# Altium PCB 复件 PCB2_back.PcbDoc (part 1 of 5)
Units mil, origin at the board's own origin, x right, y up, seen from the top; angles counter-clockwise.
Board outline 6299 x 3937 mil, 4 copper layers (TopLayer, GROUND, VCC, BottomLayer); 290 components, 470 nets, 2252 pads, 827 vias.
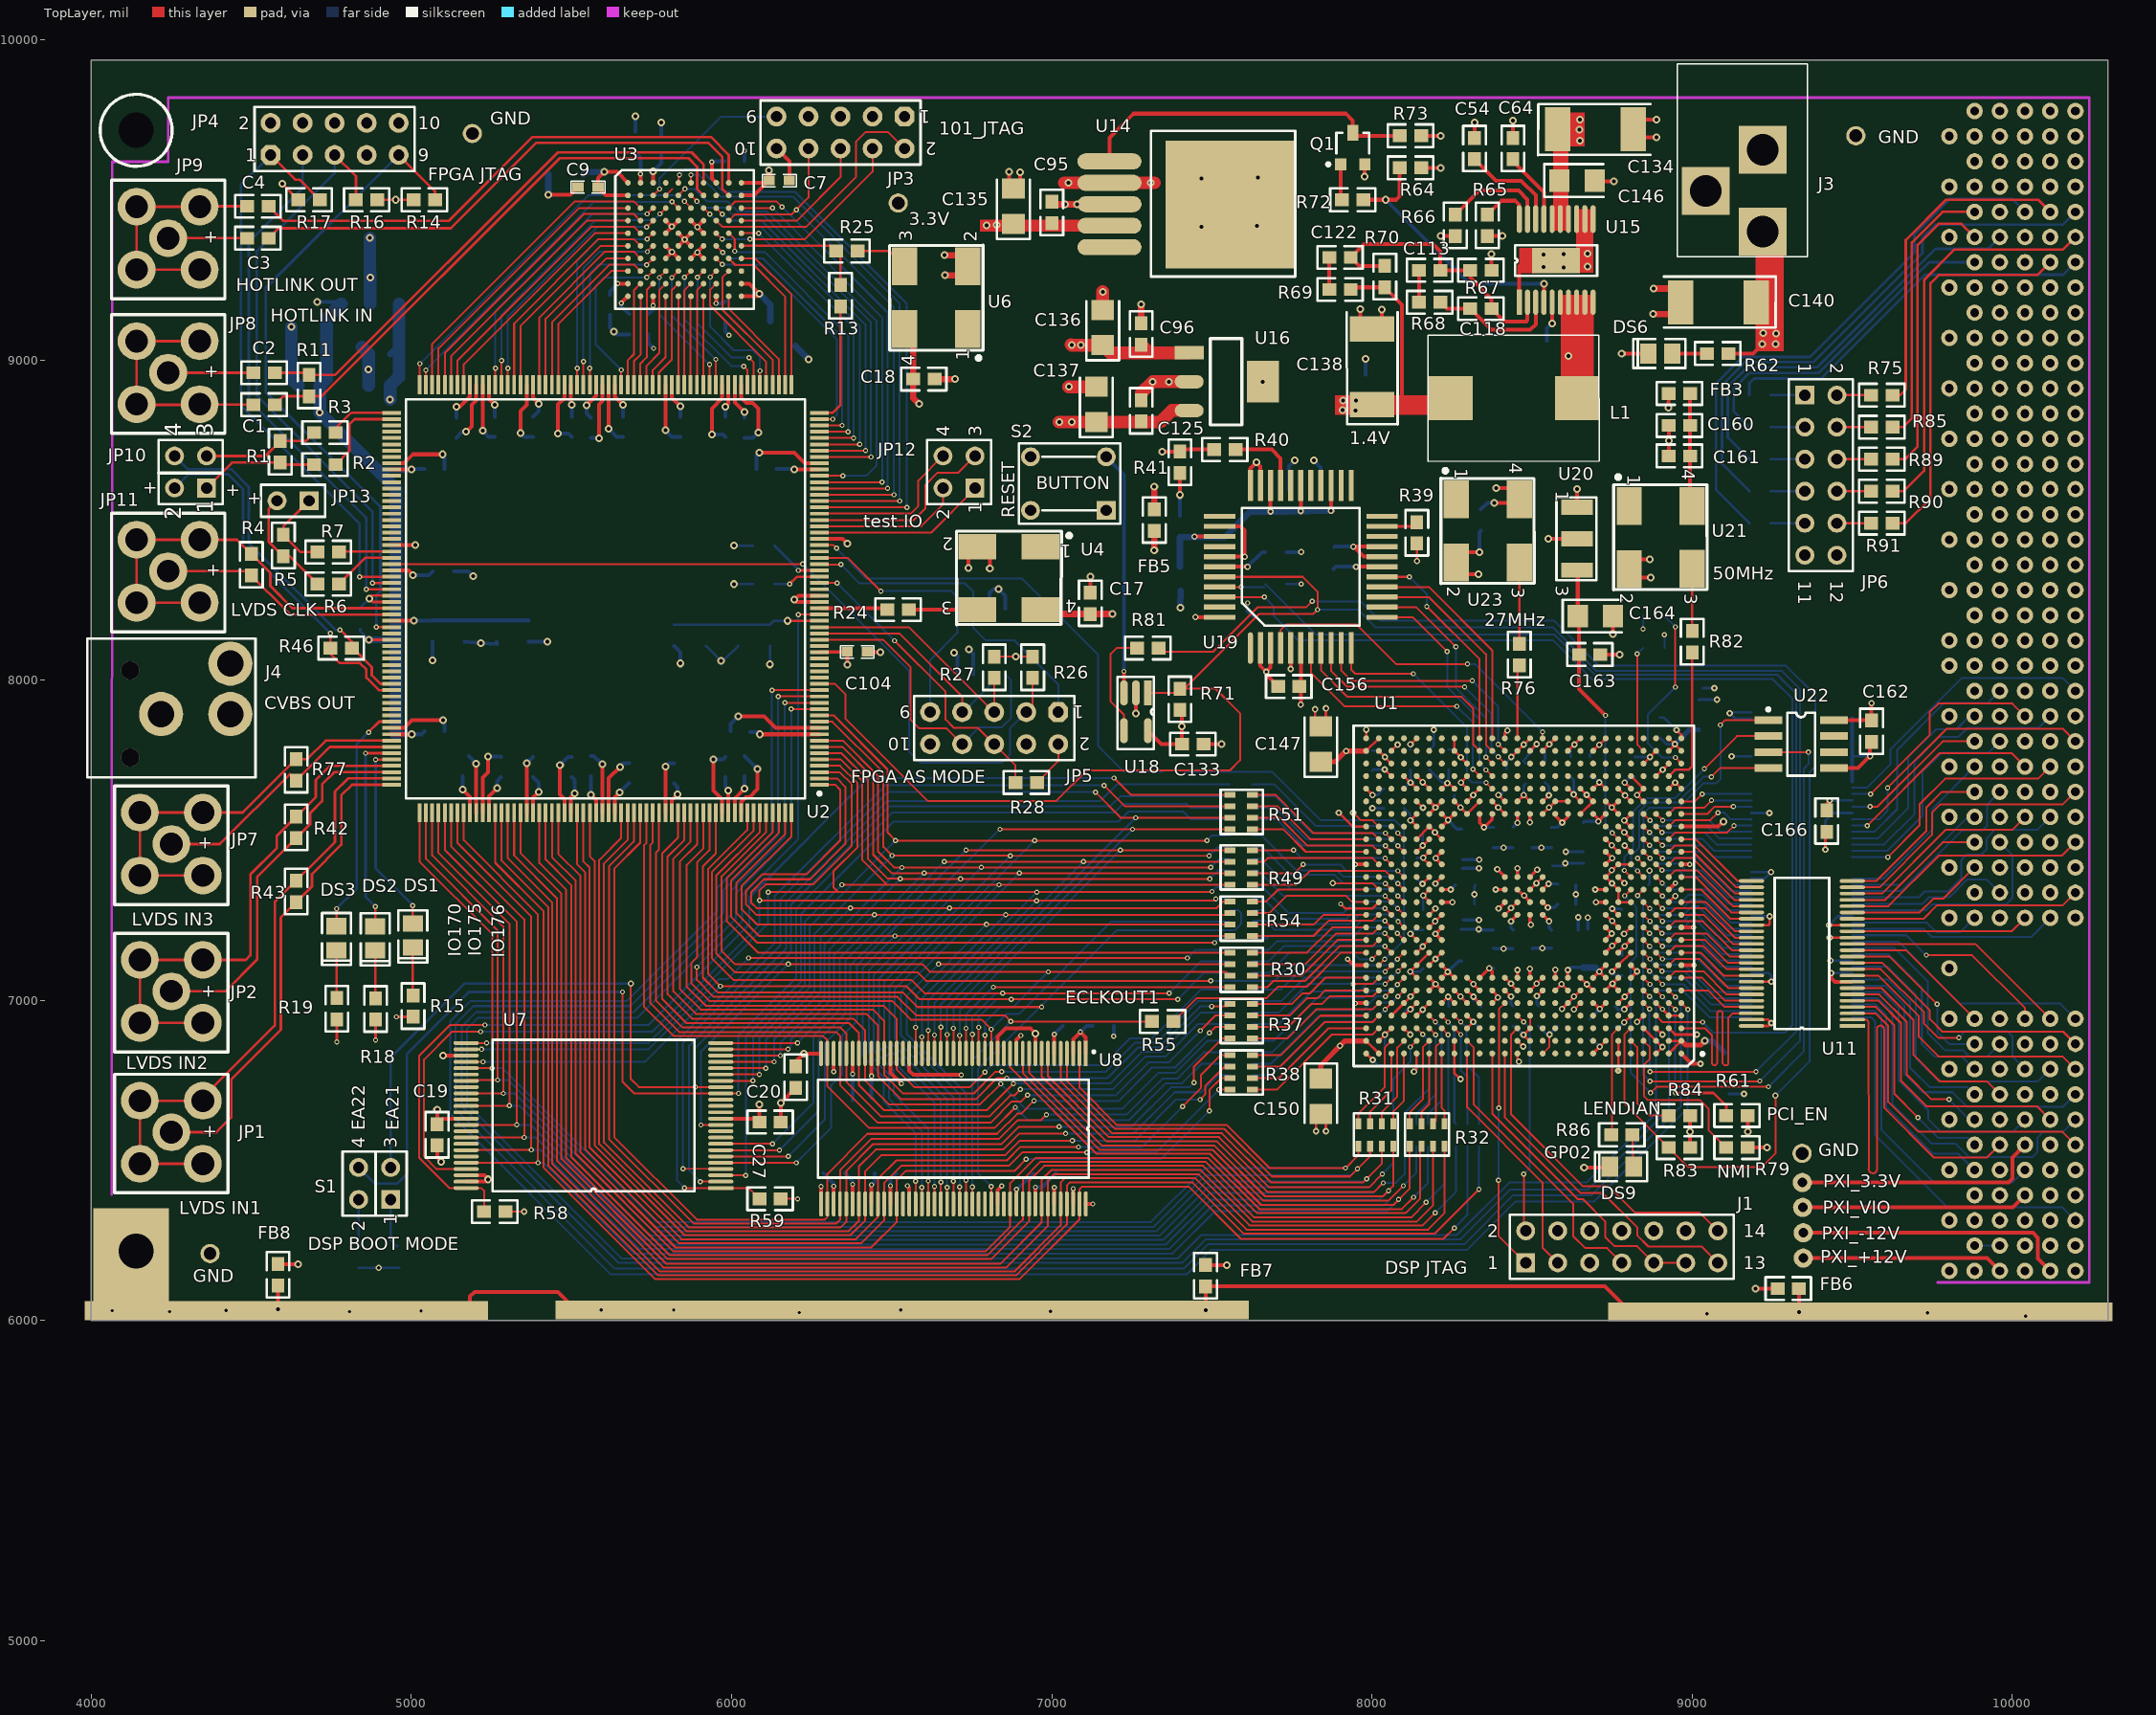
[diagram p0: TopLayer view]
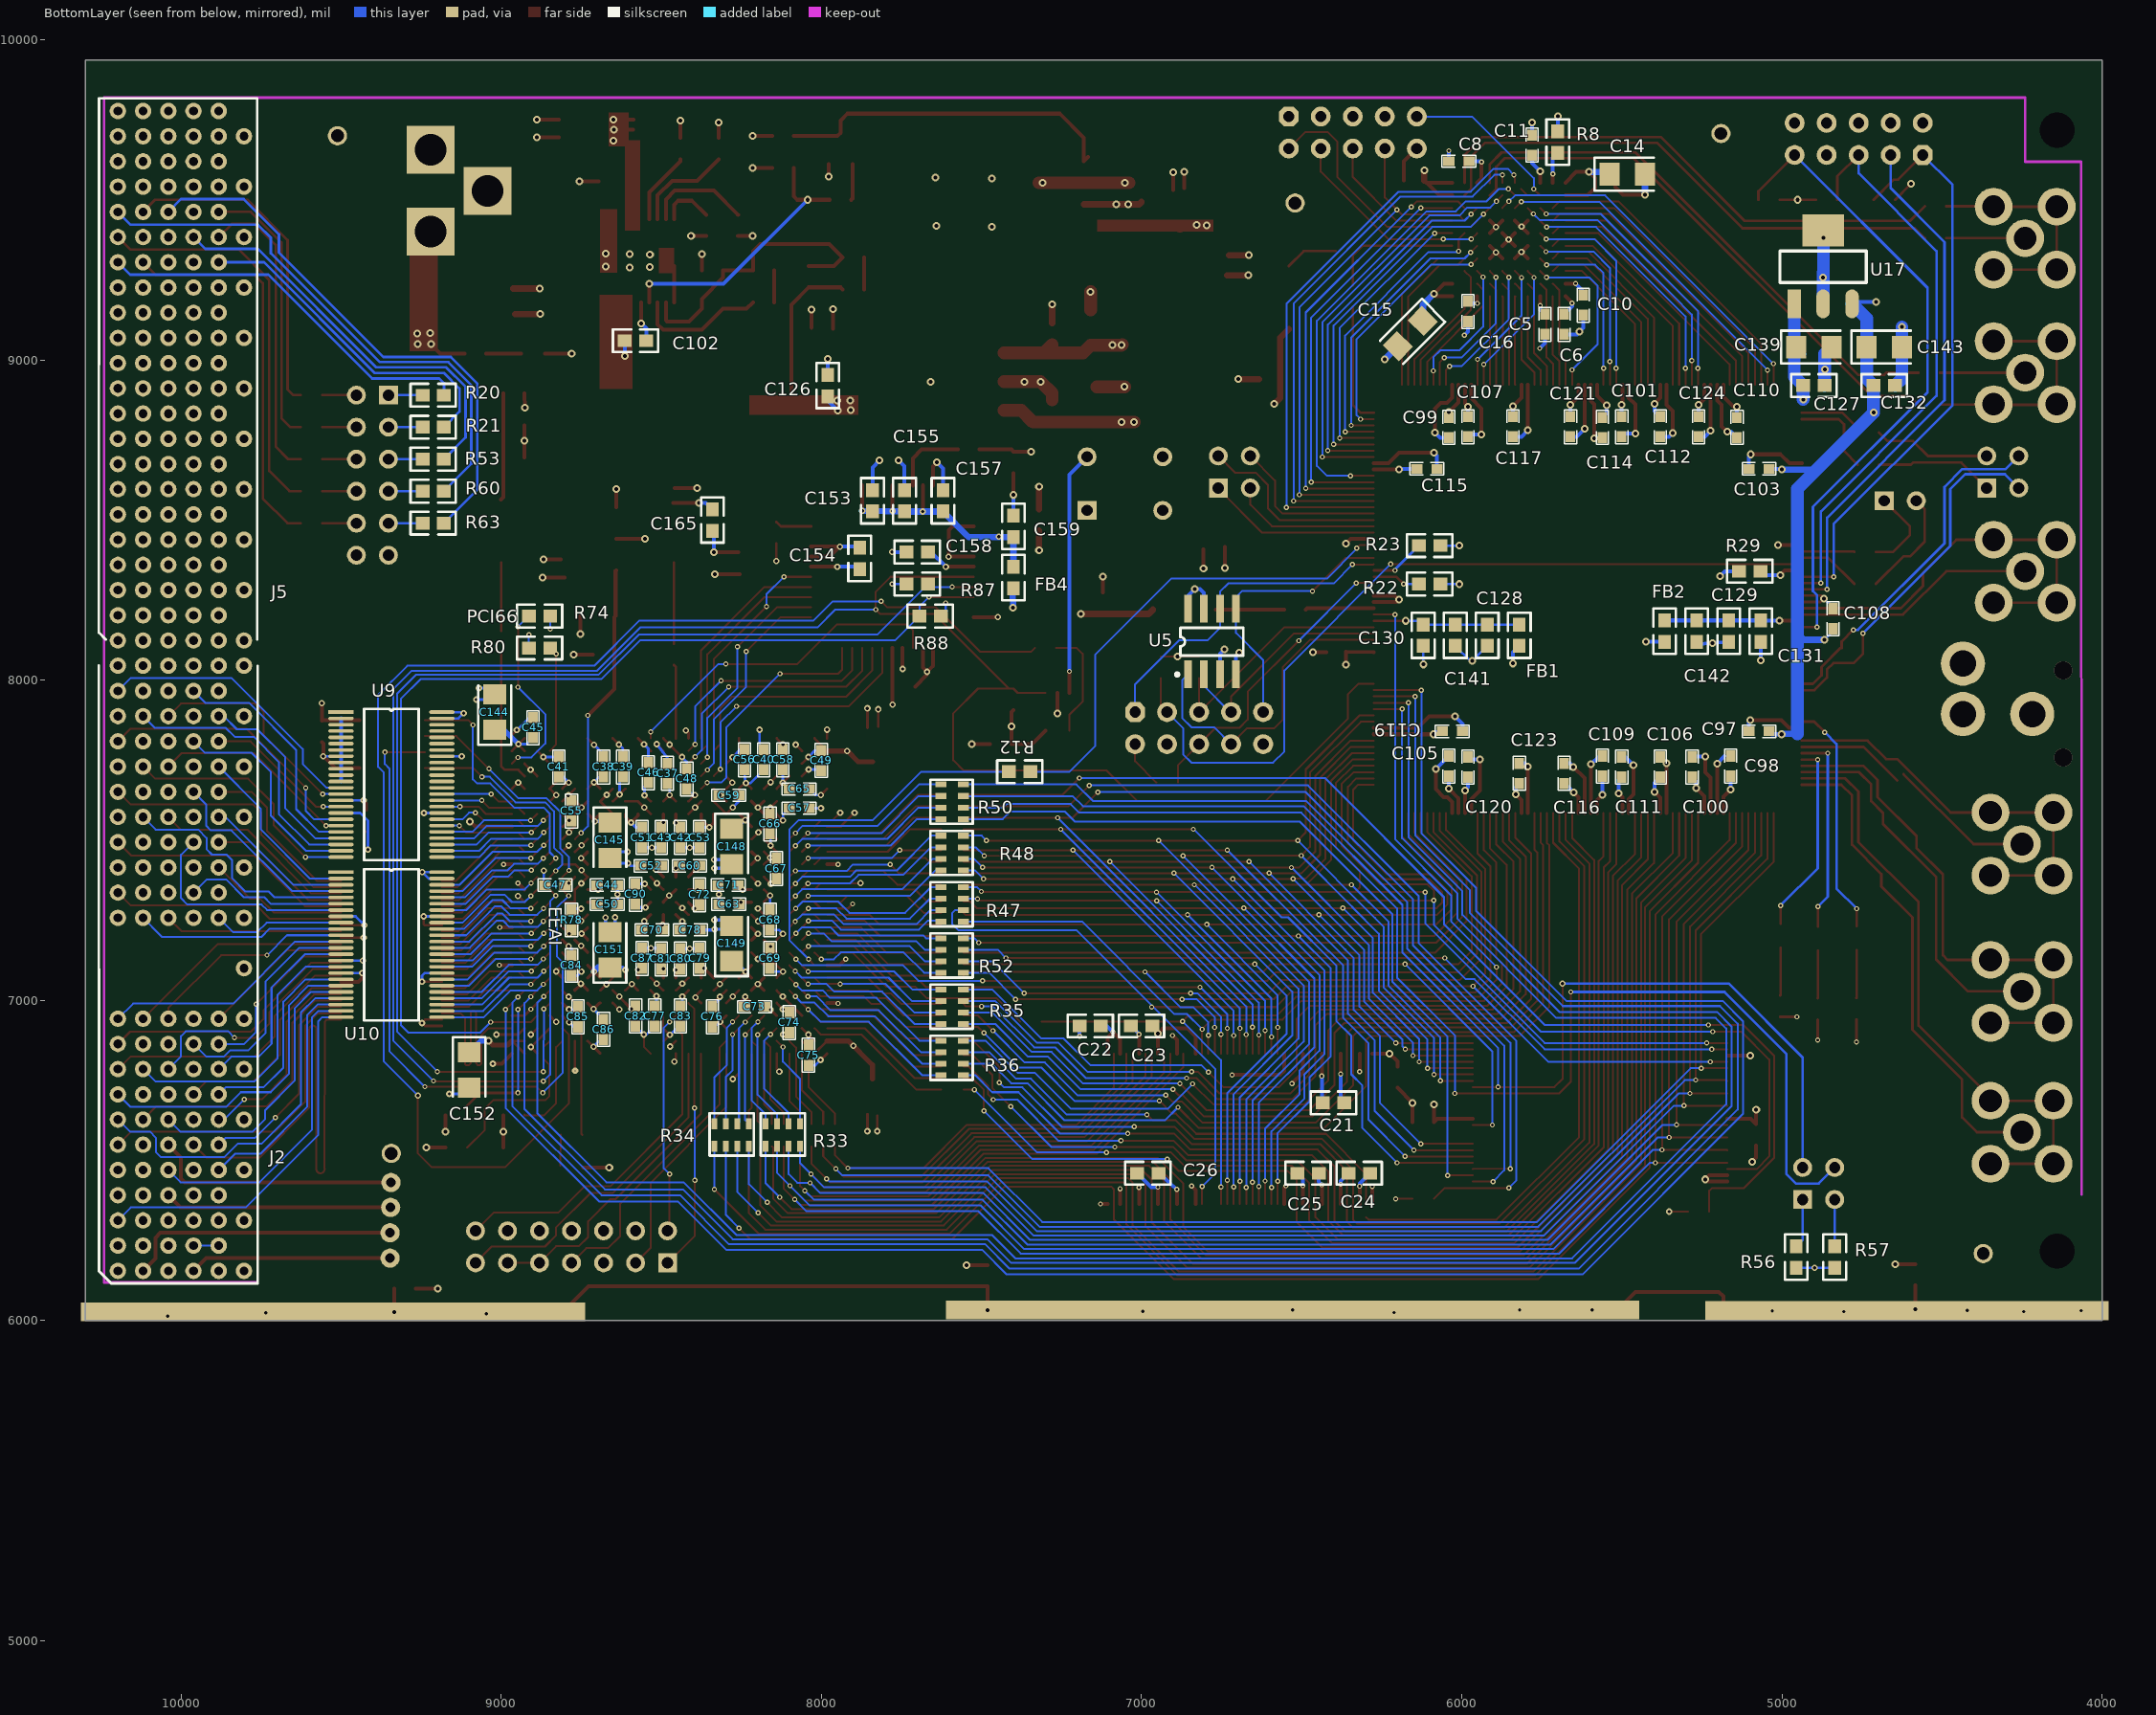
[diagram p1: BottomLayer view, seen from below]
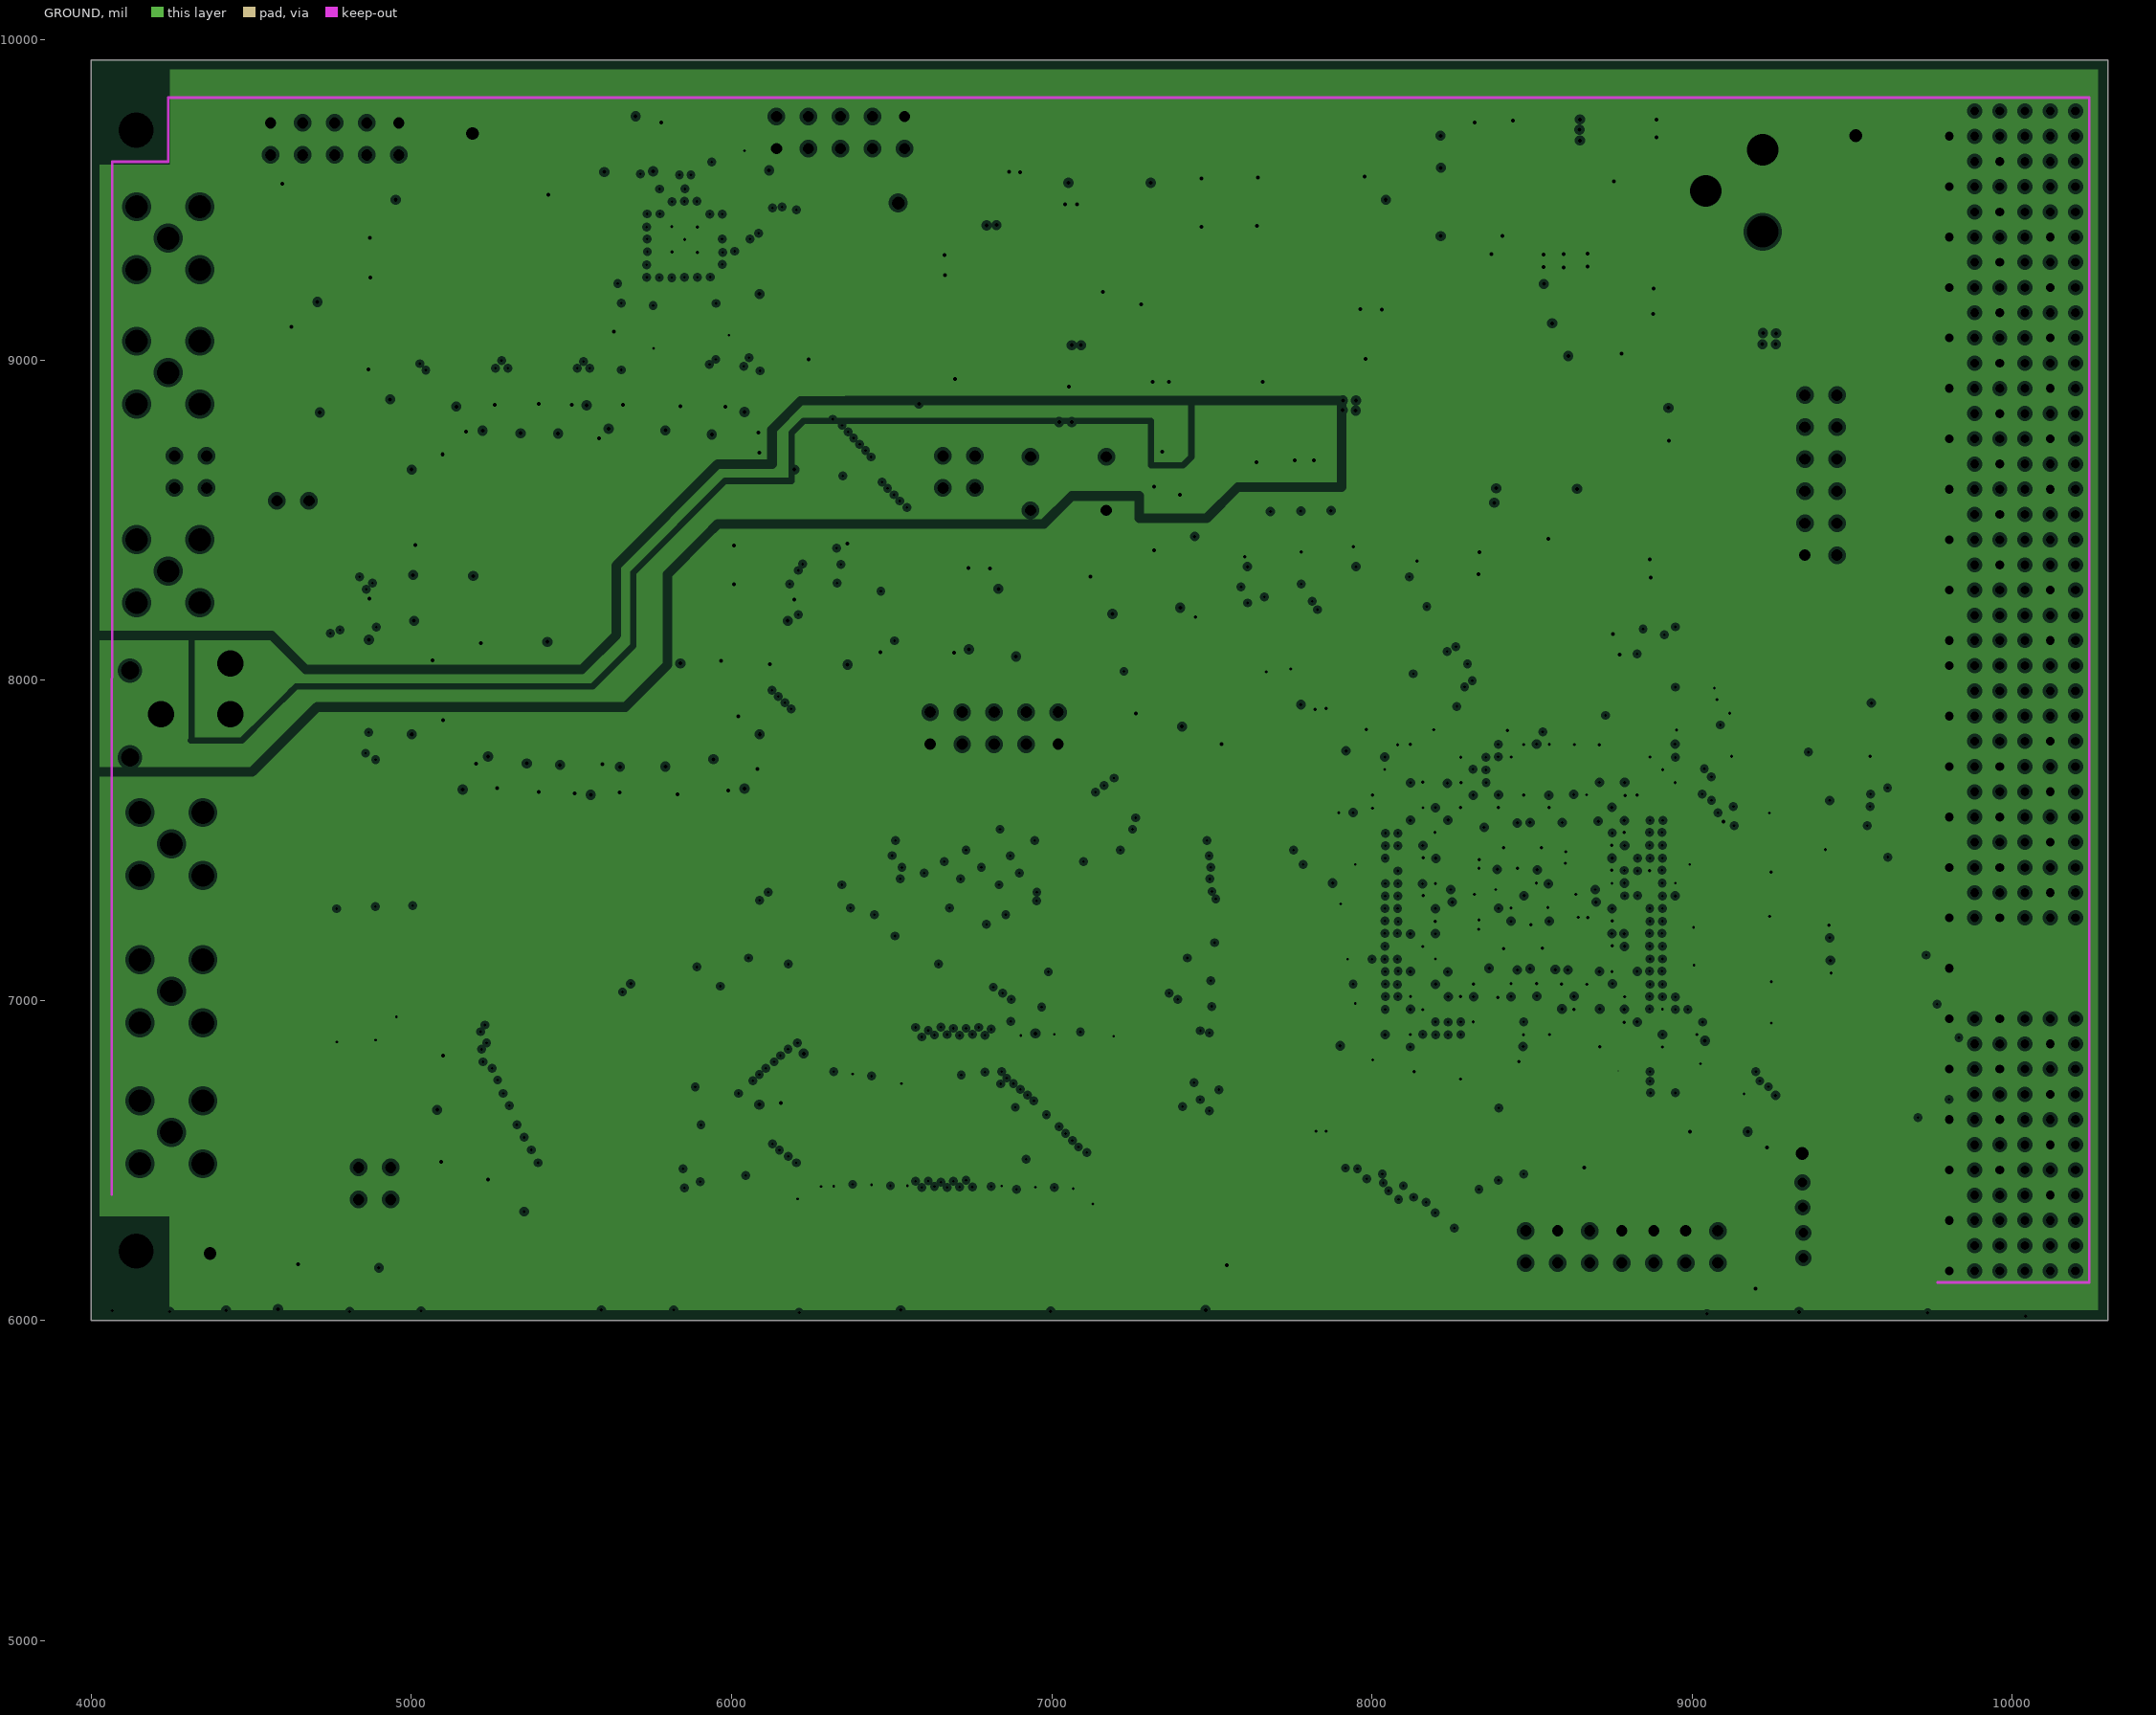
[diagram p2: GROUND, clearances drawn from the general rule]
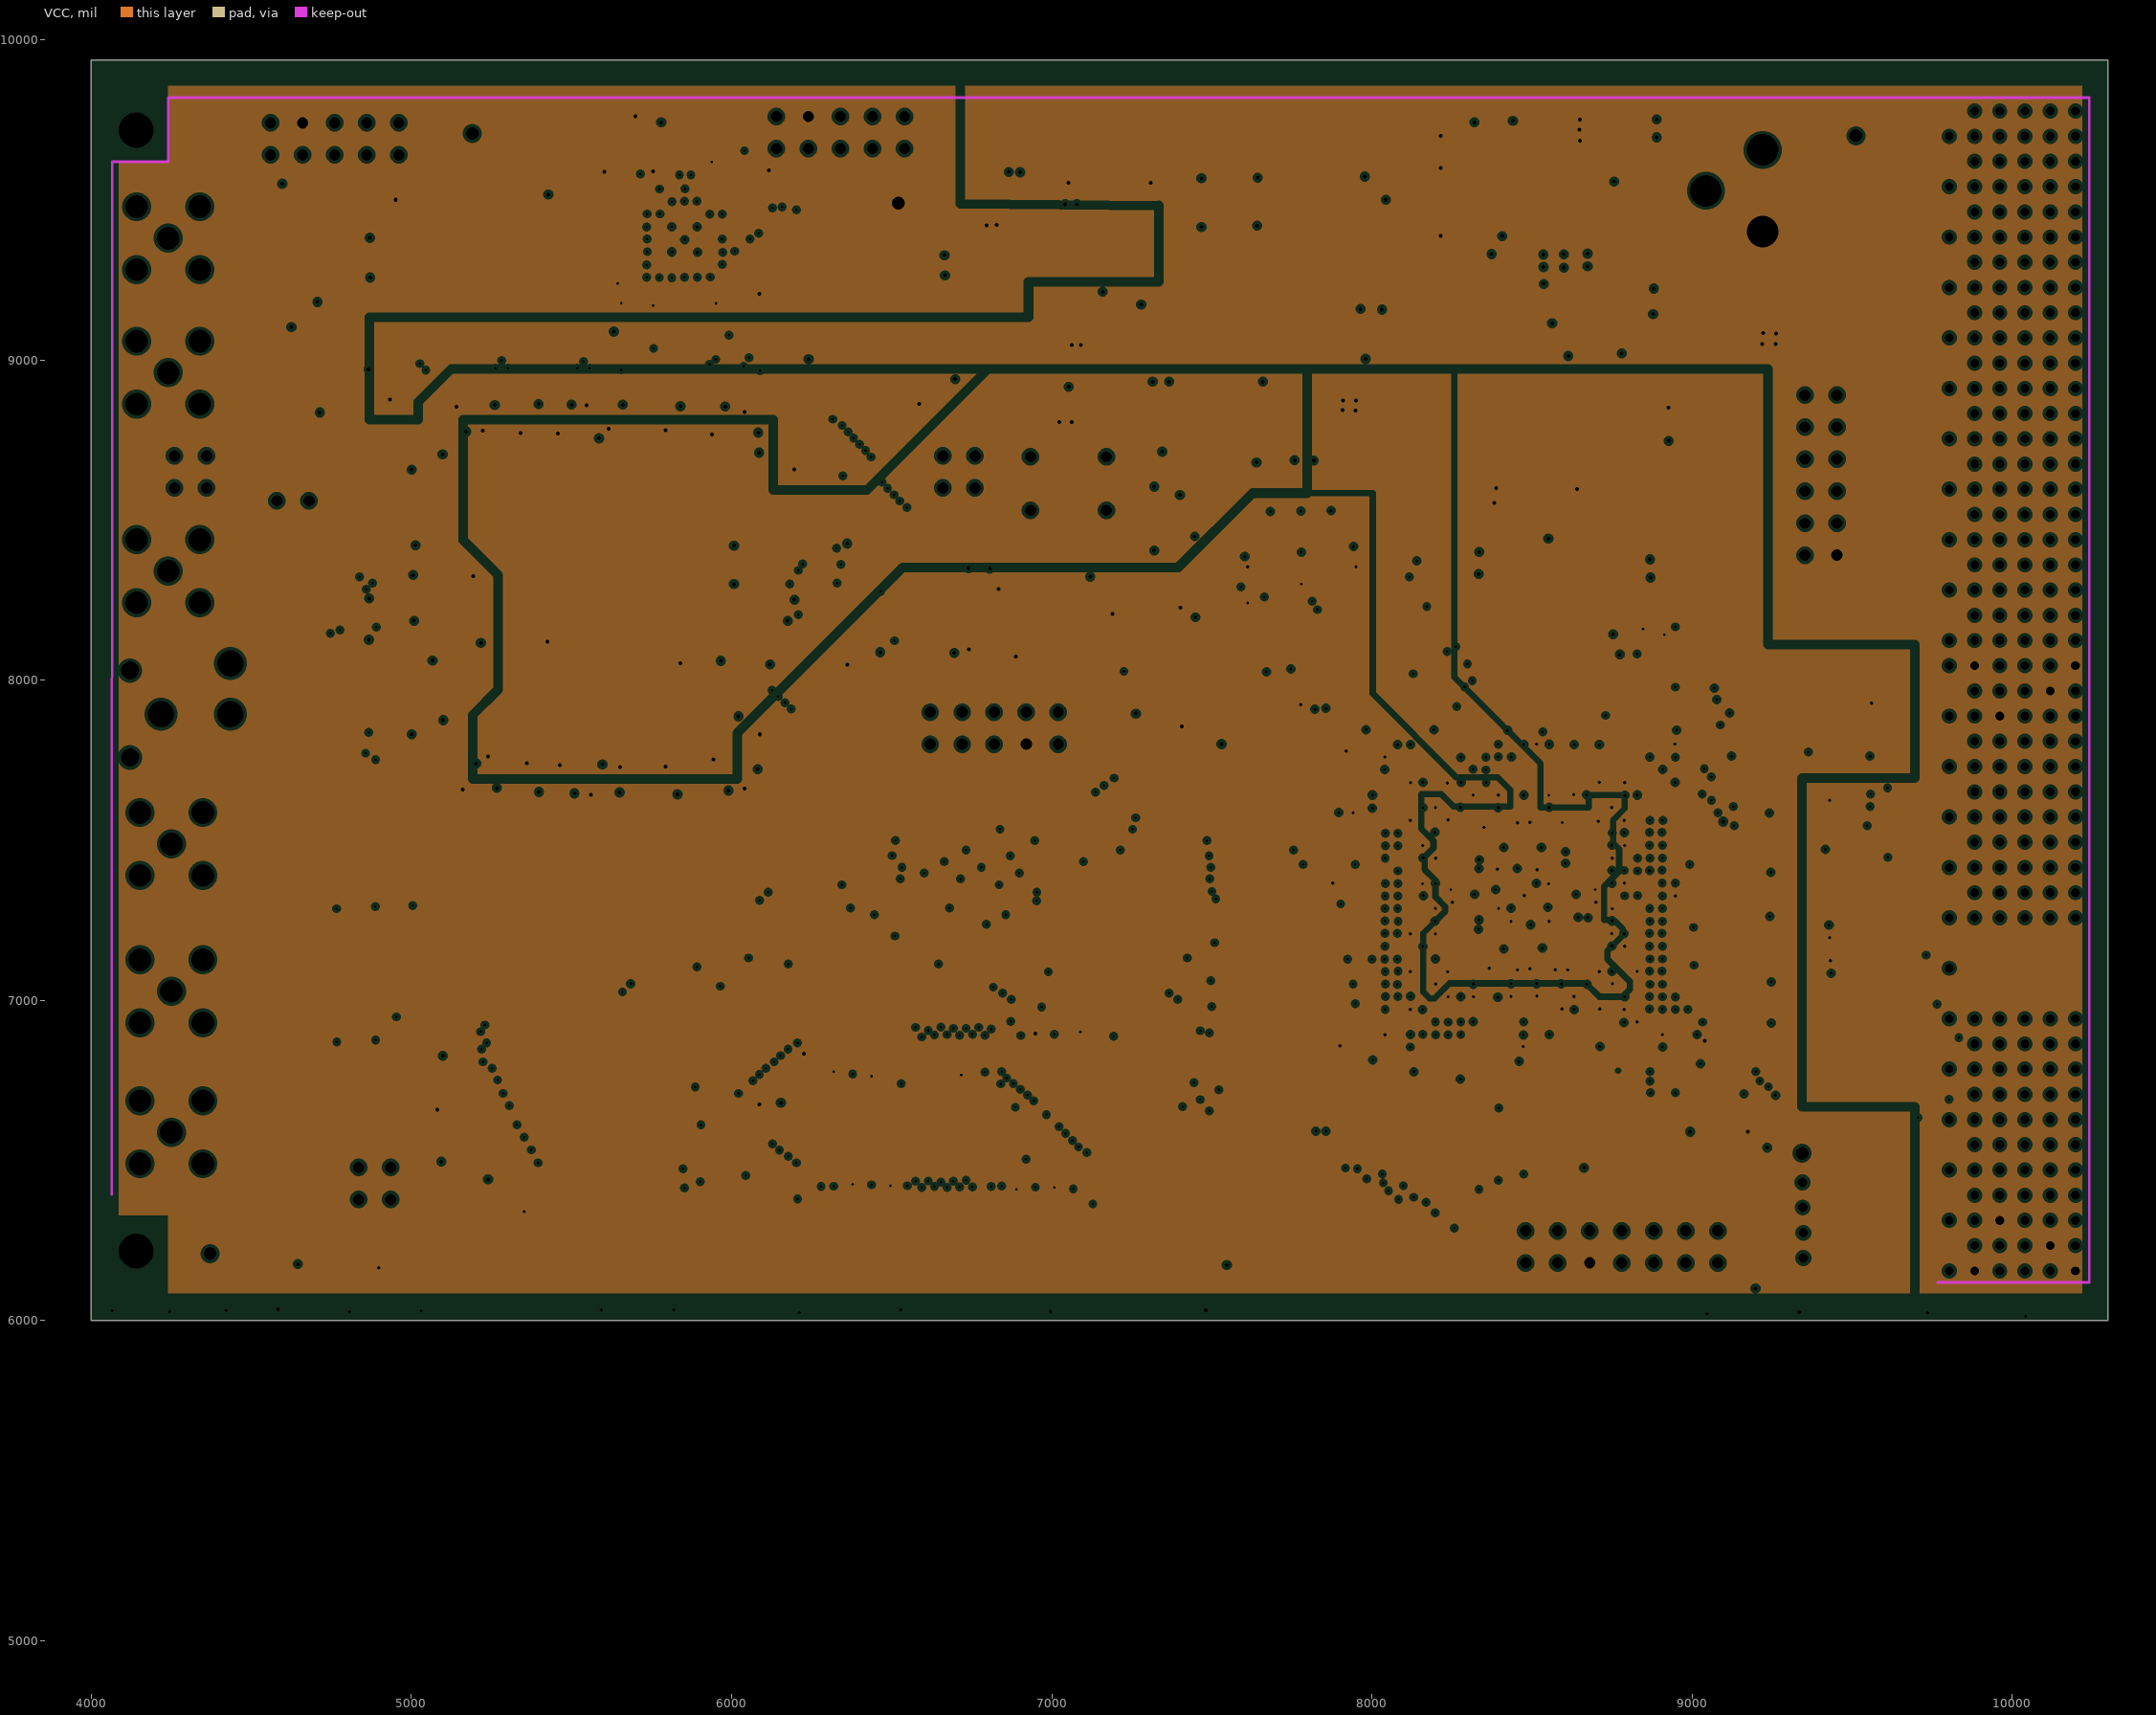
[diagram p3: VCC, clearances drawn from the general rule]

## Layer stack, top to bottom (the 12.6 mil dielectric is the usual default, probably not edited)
TopLayer: signal copper 1.4
Dielectric: core 12.6, FR-4, Dk 4.8
GROUND: plane copper 1.4, net (Multiple Nets)
Dielectric: prepreg 12.6, FR-4, Dk 4.8
VCC: plane copper 1.4, net (Multiple Nets)
Dielectric: core 12.6, FR-4, Dk 4.8
BottomLayer: signal copper 1.4

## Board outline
4000,6000 10299,6000 10299,9937 4000,9937

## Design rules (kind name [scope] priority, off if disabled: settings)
Clearance [All] p1: gap=6
ComponentClearance ComponentClearance_1 [All] p1: gap=10 collisioncheckmode=0
HoleSize HoleSize_1 [All] p1: absolutevalues=TRUE maxlimit=100 minlimit=1 maxpercent=80.000 minpercent=20.000
LayerPairs LayerPairs_1 [All] p1: enforce=TRUE
PasteMaskExpansion PasteMaskExpansion_1 [All] p1: expansion=0
PlaneClearance PlaneClearance_1 [All] p1: clearance=10
PlaneConnect [All] p1: planeconnectstyle=Relief reliefexpansion=20 reliefentries=4 reliefconductorwidth=25 reliefairgap=8
PolygonConnect PolygonConnect_1 [All] p1: connectstyle=Relief reliefconductorwidth=20 reliefentries=4 polygonreliefangle="90 Angle"
RoutingLayers [All] p1: top layer=Horizontal bottom layer=Vertical
RoutingPriority RoutingPriority_1 [All] p1: routingpriority=0
RoutingTopology RoutingTopology_1 [All] p1: topology=Shortest
RoutingVias [All] p1: holewidth=12 width=24 viastyle="Through Hole" minholewidth=8 minwidth=16 maxholewidth=28 maxwidth=50
ShortCircuit ShortCircuit_1 [All] p1: allowed=FALSE
SolderMaskExpansion SolderMaskExpansion_1 [All] p1: expansion=2
TestPointUsage TestPointUsage_1 [All] p1: valid=0 allowmultiple=FALSE
Testpoint Testpoint_1 [All] p1: side=7 testpointundercomponent=TRUE minsize=40 maxsize=100 preferedsize=60 minholesize=20 maxholesize=40 preferedholesize=32 testpointgrid=1 style=1001 order=-539222988
UnRoutedNet UnRoutedNet_1 [All] p1:
Width [All] p1: maxlimit=40 minlimit=6 preferedwidth=6 toplayer_prefwidth=8 bottomlayer_prefwidth=8 minimp=50.000000 maximp=50.000000 favimp=50.000000
7 further rules are at their usual default settings.

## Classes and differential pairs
component class U_Sheet4_DSP2_videoport: C133 C153 C154 C155 C156 C157 C158 C159 C160 C161 C162 C163 C164 C165 DS9 FB3 FB4 FB5 J4 R39 R40 R41 R71 R74 R76 R78 R79 R80 R81 R82 R83 R84 R86 R87 R88 R? S2 U1 U18 U19 U20 U21 U22 U23
component class U_Sheet3_power_clock: C37 C38 C39 C40 C41 C42 C43 C44 C45 C46 C47 C48 C49 C50 C51 C52 C53 C54 C55 C56 C57 C58 C59 C60 C63 C64 C65 C66 C67 C68 C69 C70 C71 C72 C73 C74 C75 C76 C77 C78 C79 C80 C81 C82 C83 C84 C85 C86 C87 C90 C95 C96 C97 C98 C99 C100 C101 C102 C103 C104 C105 C106 C107 C108 C109 C110 C111 C112 C113 C114 C115 C116 C117 C118 C119 C120 C121 C122 C123 C124 C125 C126 C127 C128 C129 C130 C131 C132 C134 C135 C136 C137 C138 C139 C140 C141 C142 C143 C144 C145 C146 C147 C148 C149 C150 C151 C152 DS6 FB1 FB2 J3 L1 Q1 R62 R64 R65 R66 R67 R68 R69 R70 R72 R73 U14 U15 U16 U17
component class U_Sheet2_PXI: C166 J2 J5 JP6 R20 R21 R53 R60 R61 R63 R75 R85 R89 R90 R91 U9 U10 U11
component class U_Sheet2_DSP_EMIF: C19 C20 C21 C22 C23 C24 C25 C26 C27 J1 R30 R31 R32 R33 R34 R35 R36 R37 R38 R47 R48 R49 R50 R51 R52 R54 R55 R56 R57 R58 R59 S1 U7 U8
component class U_Sheet1_FPGA2: C1 C2 C3 C4 C5 C6 C7 C8 C9 C10 C11 C14 C15 C16 C17 C18 DS1 DS2 DS3 FB6 FB7 FB8 JP1 JP2 JP3 JP4 JP5 JP7 JP8 JP9 JP10 JP11 JP12 JP13 L2 R1 R2 R3 R4 R5 R6 R7 R8 R11 R12 R13 R14 R15 R16 R17 R18 R19 R22 R23 R24 R25 R26 R27 R28 R29 R42 R43 R46 R77 U2 U3 U4 U5 U6

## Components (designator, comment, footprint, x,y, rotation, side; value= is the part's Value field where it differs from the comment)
C1 "Cap" C1608-0603 4540,8860 r180 top
C2 "Cap" C1608-0603 4540,8960 r180 top
C3 "Cap" C1608-0603 4520,9380 r180 top
C4 "Cap" C1608-0603 4520,9480 r180 top
C5 "Cap" 0603 5740,9080 r90 bottom
C6 "Cap" 0603 5680,9080 r90 bottom
C7 "Cap" 0603 6180,9560 r180 top
C8 "Cap" 0603 6040,9620 r180 bottom
C9 "Cap" 0603 5520,9540 r0 top
C10 "Cap" 0603 5620,9140 r90 bottom
C11 "Cap" 0603 5780,9702 r270 bottom
C14 "Cap Pol2" CC3216-1206 5482.31,9580 r180 bottom
C15 "Cap Pol2" CC3216-1206 6160,9082.32 r315 bottom
C16 "Cap" 0603 5980,9120 r90 bottom
C17 "Cap" C1608-0603 7120,8240 r270 top
C18 "Cap" C1608-0603 6600,8940 r180 top
C19 "Cap" C1608-0603 5080,6580 r90 top
C20 "Cap" C1608-0603 6200,6760 r90 top
C21 "Cap" C1608-0603 6400,6680 r0 bottom
C22 "Cap" C1608-0603 7160,6920 r180 bottom
C23 "Cap" C1608-0603 7000,6920 r180 bottom
C24 "Cap" C1608-0603 6320,6460 r0 bottom
C25 "Cap" C1608-0603 6480,6460 r0 bottom
C26 "Cap" C1608-0603 6980,6460 r180 bottom
C27 "Cap" C1608-0603 6120,6620 r0 top
C37 "Cap" 0603 8480,7740 r270 bottom
C38 "Cap" 0603 8680,7698 r90 bottom
C39 "Cap" 0603 8620,7698 r90 bottom
C40 "Cap" 0603 8180,7720 r90 bottom
C41 "Cap" 0603 8820,7698 r90 bottom
C42 "Cap" 0603 8440,7540 r270 bottom
C43 "Cap" 0603 8500,7540 r270 bottom
C44 "Cap" 0603 8700,7360 r180 bottom
C45 "Cap" 0603 8900,7820 r90 bottom
C46 "Cap" 0603 8540,7680 r90 bottom
C47 "Cap" 0603 8800,7360 r0 bottom
C48 "Cap" 0603 8420,7660 r90 bottom
C49 "Cap" 0603 8000,7780 r270 bottom
C50 "Cap" 0603 8700,7300 r180 bottom
C51 "Cap" 0603 8560,7540 r270 bottom
C52 "Cap" 0603 8500,7420 r0 bottom
C53 "Cap" 0603 8380,7540 r270 bottom
C54 "Cap" C1608-0603 8320,9660 r270 top
C55 "Cap" 0603 8780,7560 r90 bottom
C56 "Cap" 0603 8240,7720 r90 bottom
C57 "Cap" 0603 8100,7600 r180 bottom
C58 "Cap" 0603 8120,7720 r90 bottom
C59 "Cap" 0603 8320,7640 r180 bottom
C60 "Cap" 0603 8380,7420 r0 bottom
C63 "Cap" 0603 8320,7300 r180 bottom
C64 "Cap" C1608-0603 8440,9660 r270 top
C65 "Cap" 0603 8100,7660 r180 bottom
C66 "Cap" 0603 8160,7520 r90 bottom
C67 "Cap" 0603 8140,7380 r90 bottom
C68 "Cap" 0603 8160,7220 r90 bottom
C69 "Cap" 0603 8160,7100 r90 bottom
C70 "Cap" 0603 8560,7220 r180 bottom
C71 "Cap" 0603 8260,7360 r0 bottom
C72 "Cap" 0603 8380,7298 r90 bottom
C73 "Cap" 0603 8240,6980 r180 bottom
C74 "Cap" 0603 8100,6962 r270 bottom
C75 "Cap" 0603 8040,6860 r270 bottom
C76 "Cap" 0603 8340,6980 r270 bottom
C77 "Cap" 0603 8520,6982 r270 bottom
C78 "Cap" 0603 8378,7220 r0 bottom
C79 "Cap" 0603 8380,7100 r90 bottom
C80 "Cap" 0603 8440,7098 r90 bottom
C81 "Cap" 0603 8500,7098 r90 bottom
C82 "Cap" 0603 8580,6982 r270 bottom
C83 "Cap" 0603 8440,6982 r270 bottom
C84 "Cap" 0603 8780,7140 r270 bottom
C85 "Cap" 0603 8760,6980 r270 bottom
C86 "Cap" 0603 8680,6940 r270 bottom
C87 "Cap" 0603 8560,7100 r90 bottom
C90 "Cap" 0603 8580,7300 r90 bottom
C95 "Cap" C1608-0603 7000,9460 r270 top
C96 "Cap" C1608-0603 7279,9081 r270 top
C97 "Cap" 0603 5040,7840 r0 bottom
C98 "Cap" 0603 5160,7700 r90 bottom
C99 "Cap" 0603 6040,8820 r270 bottom
C100 "Cap" 0603 5280,7760 r270 bottom
C101 "Cap" 0603 5500,8760 r90 bottom
C102 "Cap" C1608-0603 8580,9060 r0 bottom
C103 "Cap" 0603 5040,8660 r0 bottom
C104 "Cap" 0603 6361,8088 r0 top
C105 "Cap" 0603 6040,7700 r90 bottom
C106 "Cap" 0603 5380,7760 r270 bottom
C107 "Cap" 0603 5980,8760 r90 bottom
C108 "Cap" 0603 4840,8160 r90 bottom
C109 "Cap" 0603 5560,7700 r90 bottom
C110 "Cap" 0603 5140,8820 r270 bottom
C111 "Cap" 0603 5500,7760 r270 bottom
C112 "Cap" 0603 5380,8760 r90 bottom
C113 "Cap" C1608-0603 8180,9280 r180 top
C114 "Cap" 0603 5560,8820 r270 bottom
C115 "Cap" 0603 6140,8660 r180 bottom
C116 "Cap" 0603 5680,7740 r270 bottom
C117 "Cap" 0603 5840,8760 r90 bottom
C118 "Cap" C1608-0603 8340,9160 r180 top
C119 "Cap" 0603 6060,7840 r180 bottom
C120 "Cap" 0603 5980,7760 r270 bottom
C121 "Cap" 0603 5660,8760 r90 bottom
C122 "Cap" C1608-0603 7900,9320 r180 top
C123 "Cap" 0603 5820,7740 r270 bottom
C124 "Cap" 0603 5260,8760 r90 bottom
C125 "Cap" C1608-0603 7279,8841 r270 top
C126 "Cap" C1608-0603 7980,8920 r270 bottom
C127 "Cap" C1608-0603 4900,8920 r0 bottom
C128 "Cap" C1608-0603 5920,8140 r90 bottom
C129 "Cap" C1608-0603 5166,8153 r90 bottom
C130 "Cap" C1608-0603 6120,8140 r90 bottom
C131 "Cap" C1608-0603 5066,8153 r90 bottom
C132 "Cap" C1608-0603 4680,8920 r0 bottom
C133 "Cap" C1608-0603 7440,7800 r180 top
C134 "Cap Pol1" CC6032 8580,9720 r0 top
C135 "Cap Pol1" CC3216-1206 6880,9480 r90 top
C136 "Cap Pol1" CC3216-1206 7159,9101 r90 top
C137 "Cap Pol1" CC3216-1206 7139,8861 r90 top
C138 "Cap Pol1" CC6032 8000,8860 r90 top
C139 "Cap Pol1" CC3216-1206 4900,9040 r180 bottom
C140 "Cap Pol1" CC6032 9200,9180 r180 top
C141 "Cap Pol1" C1608-0603 6020,8140 r270 bottom
C142 "Cap Pol1" C1608-0603 5266,8153 r270 bottom
C143 "Cap Pol1" CC3216-1206 4680,9040 r180 bottom
C144 "Cap Pol2" CC3216-1206 9020,7900 r90 bottom
C145 "Cap Pol2" CC3216-1206 8660,7500 r270 bottom
C146 "Cap Pol2" CC3216-1206 8640,9560 r0 top
C147 "Cap Pol2" CC3216-1206 7840,7800 r90 top
C148 "Cap Pol2" CC3216-1206 8280,7480 r270 bottom
C149 "Cap Pol2" CC3216-1206 8280,7177.69 r90 bottom
C150 "Cap Pol2" CC3216-1206 7840,6700 r270 top
C151 "Cap Pol2" CC3216-1206 8660,7157.69 r90 bottom
C152 "Cap Pol2" CC3216-1206 9100,6782.31 r270 bottom
C153 "Cap" C1608-0603 7840,8560 r270 bottom
C154 "Cap" C1608-0603 7880,8380 r270 bottom
C155 "Cap" C1608-0603 7740,8560 r270 bottom
C156 "Cap" C1608-0603 7740,7980 r0 top
C157 "Cap" C1608-0603 7620,8560 r270 bottom
C158 "Cap" C1608-0603 7700,8400 r180 bottom
C159 "Cap" C1608-0603 7400,8480 r270 bottom
C160 "Cap" C1608-0603 8960,8795 r0 top
C161 "Cap" C1608-0603 8960,8700 r0 top
C162 "Cap" C1608-0603 9560,7840 r90 top
C163 "Cap" C1608-0603 8680,8080 r180 top
C164 "Cap Pol2" CC3216-1206 8697.68,8200 r0 top
C165 "Cap" C1608-0603 8340,8500 r90 bottom
C166 "Cap" C1608-0603 9420,7560 r90 top
DS1 "LED2" "SMD _LED" 5004,7202 r90 top
DS2 "LED2" "SMD _LED" 4887,7193 r90 top
DS3 "LED2" "SMD _LED" 4766,7194 r90 top
DS6 "LED3" "SMD _LED" 8900,9020 r0 top
DS9 "LED3" "SMD _LED" 8780,6480 r0 top
FB1 "FB" C1608-0603 5820,8140 r90 bottom
FB2 "FB" C1608-0603 5366,8153 r90 bottom
FB3 "BLM18PG121SN1" C1608-0603 8960,8895 r0 top
FB4 "BLM18PG121SN1" C1608-0603 7400,8320 r270 bottom
FB5 "BLM18PG121SN1" C1608-0603 7320,8500 r270 top
FB6 "FB" C1608-0603 9300,6100 r180 top
FB7 "FB" C1608-0603 7480,6140 r90 top
FB8 "FB" C1608-0603 4583,6143 r90 top
J1 "Header 7X2 JTAG" HDR2X7 8480,6180 r0 top
J2 "352068-1" PCI2-H123 10000,7100.06 r270 bottom
J3 "PWP_CON" POWER_CON 9220,9400 r90 top
J4 "RCA" RCA 4260,7940 r0 top
J5 "352152-1" PCI2-H121 10000,8950.46 r270 bottom
JP1 "Header 2" SMA 4250,6588 r0 top
JP2 "Header 2" SMA 4250,7028 r0 top
JP3 "101_JTAG" HDR2X5 6540,9760 r180 top
JP4 "JTAG" HDR2X5 4560,9640 r0 top
JP5 "AS mode" HDR2X5 7020,7900 r180 top
JP6 "Header 6X2" HDR2X6 9352,8890 r270 top
JP7 "Header 2" SMA 4250,7488 r0 top
JP8 "Header 2" SMA 4240,8960 r0 top
JP9 "Header 2" SMA 4240,9380 r0 top
JP10 "Header 2X2" HDR2X2 4360,8600 r90 top
JP11 "Header 2" SMA 4240,8340 r0 top
JP12 "Header 2X2" HDR2X2 6760,8600 r90 top
JP13 "Header 2" HDR1X2 4680,8560 r180 top
L1 "Inductor Iron" L44.7uH 8640,8880 r180 top
Q1 "QNPN3904" "SO-G3 for NPN" 7940,9660 r0 top
R1 "Res2" C1608-0603 4590,8713 r270 top
R2 "Res2" C1608-0603 4730,8673 r0 top
R3 "Res2" C1608-0603 4730,8773 r0 top
R4 "Res2" C1608-0603 4500,8360 r270 top
R5 "Res2" C1608-0603 4600,8420 r270 top
R6 "Res2" C1608-0603 4740,8300 r0 top
R7 "Res2" C1608-0603 4740,8400 r0 top
R8 "Res2" C1608-0603 5700,9680 r90 bottom
R11 "Res2" C1608-0603 4680,8920 r270 top
R12 "Res1" CR1608-0603 7380,7714 r0 bottom
R13 "Res2" C1608-0603 6340,9200 r270 top
R14 "Res2" C1608-0603 5040,9500 r180 top
R15 "Res2" C1608-0603 5005,6982 r270 top
R16 "Res2" C1608-0603 4860,9500 r0 top
R17 "Res2" C1608-0603 4680,9500 r0 top
R18 "Res2" C1608-0603 4888,6973 r270 top
R19 "Res2" C1608-0603 4767,6974 r270 top
R20 "Res1" CR1608-0603 9212,8890 r180 bottom
R21 "Res1" CR1608-0603 9212,8790 r180 bottom
R22 "Res2" C1608-0603 6100,8300 r0 bottom
R23 "Res2" C1608-0603 6100,8420 r0 bottom
R24 "Res2" C1608-0603 6520,8220 r180 top
R25 "Res2" C1608-0603 6360,9340 r180 top
R26 "Res2" C1608-0603 6940,8040 r90 top
R27 "Res2" C1608-0603 6820,8040 r90 top
R28 "Res2" C1608-0603 6920,7680 r180 top
R29 "Res2" C1608-0603 5100,8340 r0 bottom
R30 "R0604_4" R0603_4 7626,7041 r180 top
R31 "R0604_4" R0603_4 8066,6614 r270 top
R32 "R0604_4" R0603_4 8226,6614 r270 top
R33 "R0604_4" R0603_4 8066,6614 r270 bottom
R34 "R0604_4" R0603_4 8226,6614 r270 bottom
R35 "R0604_4" R0603_4 7626,7034 r180 bottom
R36 "R0604_4" R0603_4 7626,6874 r180 bottom
R37 "R0604_4" R0603_4 7626,6881 r180 top
R38 "R0604_4" R0603_4 7626,6721 r180 top
R39 "Res1" CR1608-0603 8140,8460 r270 top
R40 "Res1" CR1608-0603 7540,8720 r180 top
R41 "Res1" CR1608-0603 7400,8680 r90 top
R42 "Res2" C1608-0603 4640,7540 r270 top
R43 "Res2" C1608-0603 4640,7340 r270 top
R46 "Res2" C1608-0603 4780,8100 r180 top
R47 "R0604_4" R0603_4 7626,7354 r180 bottom
R48 "R0604_4" R0603_4 7626,7514 r180 bottom
R49 "R0604_4" R0603_4 7626,7361 r180 top
R50 "R0604_4" R0603_4 7626,7674 r180 bottom
R51 "R0604_4" R0603_4 7626,7534 r180 top
R52 "R0604_4" R0603_4 7626,7194 r180 bottom
R53 "Res1" CR1608-0603 9212,8690 r180 bottom
R54 "R0604_4" R0603_4 7626,7201 r180 top
R55 "Res1" CR1608-0603 7346,6934 r180 top
R56 "Res1" CR1608-0603 4955,6198 r90 bottom
R57 "Res1" CR1608-0603 4835,6198 r90 bottom
R58 "Res1" CR1608-0603 5260,6340 r0 top
R59 "Res1" CR1608-0603 6120,6380 r180 top
R60 "Res1" CR1608-0603 9212,8590 r180 bottom
R61 "Res1" CR1608-0603 9140,6640 r0 top
R62 "Res2" CR1608-0603 9080,9020 r0 top
R63 "Res1" CR1608-0603 9212,8490 r180 bottom
R64 "Res1" CR1608-0603 8120,9600 r180 top
R65 "Res1" CR1608-0603 8360,9420 r90 top
R66 "Res1" CR1608-0603 8260,9420 r270 top
R67 "Res1" CR1608-0603 8340,9280 r180 top
R68 "Res1" CR1608-0603 8180,9180 r0 top
R69 "Res1" CR1608-0603 7900,9220 r0 top
R70 "Res1" CR1608-0603 8040,9260 r270 top
R71 "Res1" CR1608-0603 7400,7940 r270 top
R72 "Res3" CR1608-0603 7940,9500 r0 top
R73 "Res3" CR1608-0603 8120,9700 r0 top
R74 "Res1" CR1608-0603 8880,8200 r180 bottom
R75 "Res1" CR1608-0603 9592,8890 r180 top
R76 "Res1" CR1608-0603 8460,8080 r270 top
R77 "Res2" C1608-0603 4640,7720 r270 top
R78 "Res1" 0603 8780,7220 r90 bottom
R79 "Res1" CR1608-0603 9140,6540 r180 top
R80 "Res1" CR1608-0603 8880,8100 r0 bottom
R81 "Res1" CR1608-0603 7300,8100 r0 top
R82 "Res1" CR1608-0603 9000,8120 r270 top
R83 "Res1" CR1608-0603 8960,6540 r180 top
R84 "Res1" CR1608-0603 8960,6640 r180 top
R85 "Res1" CR1608-0603 9592,8790 r180 top
R86 "Res1" CR1608-0603 8780,6580 r0 top
R87 "Res1" CR1608-0603 7700,8300 r180 bottom
R88 "Res1" CR1608-0603 7660,8200 r0 bottom
R89 "Res1" CR1608-0603 9592,8690 r180 top
R90 "Res1" CR1608-0603 9592,8590 r180 top
R91 "Res1" CR1608-0603 9592,8490 r180 top
S1 "SW DIP-2" HEADER2X2 4935,6378 r90 top
S2 "SW-PB" BUTTON 7020,8580 r90 top
U1 "TMS320DM642" GNZ548 8966,6834 r0 top locked
U2 "EP1C12Q240C6" PQFP240 5606,8254 r180 top locked
U3 "CYP15G0101" BGA100x10 5676,9553 r0 top locked
U4 "Oscillator   27MHz" OSC 6880,8220 r270 top
U5 "EPCS1SI8" SOIC8 6780,8120 r180 bottom
U6 "Oscillator   20MHz" OSC 6540,9180 r180 top
U7 "Am29LV800B" TSOP48 5966,6414 r180 top locked
U8 "HY57V283220" TSOP86 7106,6834 r270 top locked
U9 "SN74CBT16210" SSOP48 9500,7900 r180 bottom
U10 "SN74CBT16210" SSOP48 9500,7400 r180 bottom
U11 "SN74CBT16210" SSOP48 9500,6920 r180 top
U14 "TPS75733" SOT23-5S 7180,9620 r0 top
U15 "TPS54310" PWP20 8460,9180 r90 top
U16 "AS1117-1.5V" LM1117 7679,8881 r0 top
U17 "AS1117-2.5V" LM1117 4820,9425 r90 bottom
U18 "TPS3823-33" DBV5 7300,7960 r270 top
U19 "SAA7121H" QFP44_2 7620,8100 r90 top
U20 "ACF451832" ACF451832 8640,8540 r270 top
U21 "Oscillator" OSC50MHz 9000,8460 r0 top
U22 "93C66B" SO-G8 9340,7800 r270 top
U23 "Oscillator" OSC50MHz 8460,8480 r0 top

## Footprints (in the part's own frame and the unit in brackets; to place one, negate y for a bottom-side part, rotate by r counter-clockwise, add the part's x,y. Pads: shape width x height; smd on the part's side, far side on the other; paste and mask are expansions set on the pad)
0603 [mil] "for DSP"
  rect 35x30 smd: 1(0,0) 2(62.99,0)
  silkscreen extent -22,-19 84,19
ACF451832 [mm] "for ACF451832-333-T"
  rect 1.2x2.5 smd: 1(0,0) 2(2.5,0) 3(5,0)
  silkscreen extent -0.76,-1.63 5.79,1.55
BGA100x10 [mm] "for CYP15G0101"
  round 0.45 smd: A1(0,0) A2(1,0) A3(2,0) A4(3,0) A5(4,0) A6(5,0) A7(6,0) A8(7,0) A9(8,0) A10(9,0) B1(0,-1) B2(1,-1) B3(2,-1) B4(3,-1) B5(4,-1) B6(5,-1) B7(6,-1) B8(7,-1) B9(8,-1) B10(9,-1) C1(0,-2) C2(1,-2) C3(2,-2) C4(3,-2) C5(4,-2) C6(5,-2) C7(6,-2) C8(7,-2) C9(8,-2) C10(9,-2) D1(0,-3) D2(1,-3) D3(2,-3) D4(3,-3) D5(4,-3) D6(5,-3) D7(6,-3) D8(7,-3) D9(8,-3) D10(9,-3) E1(0,-4) E2(1,-4) E3(2,-4) E4(3,-4) E5(4,-4) E6(5,-4) E7(6,-4) E8(7,-4) E9(8,-4) E10(9,-4) F1(0,-5) F2(1,-5) F3(2,-5) F4(3,-5) F5(4,-5) F6(5,-5) F7(6,-5) F8(7,-5) F9(8,-5) F10(9,-5) G1(0,-6) G2(1,-6) G3(2,-6) G4(3,-6) G5(4,-6) G6(5,-6) G7(6,-6) G8(7,-6) G9(8,-6) G10(9,-6) H1(0,-7) H2(1,-7) H3(2,-7) H4(3,-7) H5(4,-7) H6(5,-7) H7(6,-7) H8(7,-7) H9(8,-7) H10(9,-7) J1(0,-8) J2(1,-8) J3(2,-8) J4(3,-8) J5(4,-8) J6(5,-8) J7(6,-8) J8(7,-8) J9(8,-8) J10(9,-8) K1(0,-9) K2(1,-9) K3(2,-9) K4(3,-9) K5(4,-9) K6(5,-9) K7(6,-9) K8(7,-9) K9(8,-9) K10(9,-9)
  silkscreen extent -1,-10 10,1
BUTTON [mm]
  rect 1.5x1.5 hole 0.9: 1(-1.27,-3.81)
  round 1.5 hole 0.9: 2(2.98,-3.81) 3(2.98,2.2) 4(-1.27,2.2)
  silkscreen extent -2.34,-4.93 4.04,3.12
C1608-0603 [mm]
  rect 1.1x1 smd: 1(-0.85,0) 2(0.85,0)
  silkscreen extent -1.8,-0.9 1.8,0.9
CC3216-1206 [mm]
  rect 1.6x1.8 smd: 1(-1.4,0) 2(1.4,0)
  silkscreen extent -2.6,-1.3 2.1,1.3
CC6032 [mm] "for 100uF"
  rect 2x3.5 smd: 1(0,0) 2(6,0)
  silkscreen extent -1.56,-2.03 7.34,2.01
CR1608-0603 [mm]
  rect 1.1x1 smd: 1(-0.85,0) 2(0.85,0)
  silkscreen extent -1.8,-0.9 1.8,0.9
DBV5 [mm] "DBV5;DBV (R-PDSO-G5);PSO;for TPS3823-33"
  rect 2x0.6 smd: 1(0,0)
  oval 2x0.6 smd: 2(0,-0.95) 3(0,-1.9) 4(3,-1.9) 5(3,0)
  silkscreen extent -1.27,-2.41 4.45,0.48
GNZ548 [mm] "BGA;548 Balls;Body 27 x 27 mm;for DM642"
  round 0.47 smd: A1(0,0) A2(-1,0) A3(-2,0) A4(-3,0) A5(-4,0) A6(-5,0) A7(-6,0) A8(-7,0) A9(-8,0) A10(-9,0) A11(-10,0) A12(-11,0) A13(-12,0) A14(-13,0) A15(-14,0) A16(-15,0) A17(-16,0) A18(-17,0) A19(-18,0) A20(-19,0) A21(-20,0) A22(-21,0) A23(-22,0) A24(-23,0) A25(-24,0) A26(-25,0) AA1(0,20) AA2(-1,20) AA3(-2,20) AA4(-3,20) AA5(-4,20) AA6(-5,20) AA7(-6,20) AA8(-7,20) AA9(-8,20) AA10(-9,20) AA11(-10,20) AA12(-11,20) AA13(-12,20) AA14(-13,20) AA15(-14,20) AA16(-15,20) AA17(-16,20) AA18(-17,20) AA19(-18,20) AA20(-19,20) AA21(-20,20) AA22(-21,20) AA23(-22,20) AA24(-23,20) AA25(-24,20) AA26(-25,20) AB1(0,21) AB2(-1,21) AB3(-2,21) AB4(-3,21) AB5(-4,21) AB6(-5,21) AB7(-6,21) AB8(-7,21) AB9(-8,21) AB10(-9,21) AB11(-10,21) AB12(-11,21) AB13(-12,21) AB14(-13,21) AB15(-14,21) AB16(-15,21) AB17(-16,21) AB18(-17,21) AB19(-18,21) AB20(-19,21) AB21(-20,21) AB22(-21,21) AB23(-22,21) AB24(-23,21) AB25(-24,21) AB26(-25,21) AC1(0,22) AC2(-1,22) AC3(-2,22) AC4(-3,22) AC5(-4,22) AC6(-5,22) AC7(-6,22) AC8(-7,22) AC9(-8,22) AC10(-9,22) AC11(-10,22) AC12(-11,22) AC13(-12,22) AC14(-13,22) AC15(-14,22) AC16(-15,22) AC17(-16,22) AC18(-17,22) AC19(-18,22) AC20(-19,22) AC21(-20,22) AC22(-21,22) AC23(-22,22) AC24(-23,22) AC25(-24,22) AC26(-25,22) AD1(0,23) AD2(-1,23) AD3(-2,23) AD4(-3,23) AD5(-4,23) AD6(-5,23) AD7(-6,23) AD8(-7,23) AD9(-8,23) AD10(-9,23) AD11(-10,23) AD12(-11,23) AD13(-12,23) AD14(-13,23) AD15(-14,23) AD16(-15,23) AD17(-16,23) AD18(-17,23) AD19(-18,23) AD20(-19,23) AD21(-20,23) AD22(-21,23) AD23(-22,23) AD24(-23,23) AD25(-24,23) AD26(-25,23) AE1(0,24) AE2(-1,24) AE3(-2,24) AE4(-3,24) AE5(-4,24) AE6(-5,24) AE7(-6,24) AE8(-7,24) AE9(-8,24) AE10(-9,24) AE11(-10,24) AE12(-11,24) AE13(-12,24) AE14(-13,24) AE15(-14,24) AE16(-15,24) AE17(-16,24) AE18(-17,24) AE19(-18,24) AE20(-19,24) AE21(-20,24) AE22(-21,24) AE23(-22,24) AE24(-23,24) AE25(-24,24) AE26(-25,24) AF1(0,25) AF2(-1,25) AF3(-2,25) AF4(-3,25) AF5(-4,25) AF6(-5,25) AF7(-6,25) AF8(-7,25) AF9(-8,25) AF10(-9,25) AF11(-10,25) AF12(-11,25) AF13(-12,25) AF14(-13,25) AF15(-14,25) AF16(-15,25) AF17(-16,25) AF18(-17,25) AF19(-18,25) AF20(-19,25) AF21(-20,25) AF22(-21,25) AF23(-22,25) AF24(-23,25) AF25(-24,25) AF26(-25,25) B1(0,1) B2(-1,1) B3(-2,1) B4(-3,1) B5(-4,1) B6(-5,1) B7(-6,1) B8(-7,1) B9(-8,1) B10(-9,1) B11(-10,1) B12(-11,1) B13(-12,1) B14(-13,1) B15(-14,1) B16(-15,1) B17(-16,1) B18(-17,1) B19(-18,1) B20(-19,1) B21(-20,1) B22(-21,1) B23(-22,1) B24(-23,1) B25(-24,1) B26(-25,1) C1(0,2) C2(-1,2) C3(-2,2) C4(-3,2) C5(-4,2) C6(-5,2) C7(-6,2) C8(-7,2) C9(-8,2) C10(-9,2) C11(-10,2) C12(-11,2) C13(-12,2) C14(-13,2) C15(-14,2) C16(-15,2) C17(-16,2) C18(-17,2) C19(-18,2) C20(-19,2) C21(-20,2) C22(-21,2) C23(-22,2) C24(-23,2) C25(-24,2) C26(-25,2) D1(0,3) D2(-1,3) D3(-2,3) D4(-3,3) D5(-4,3) D6(-5,3) D7(-6,3) D8(-7,3) D9(-8,3) D10(-9,3) D11(-10,3) D12(-11,3) D13(-12,3) D14(-13,3) D15(-14,3) D16(-15,3) D17(-16,3) D18(-17,3) D19(-18,3) D20(-19,3) D21(-20,3) D22(-21,3) D23(-22,3) D24(-23,3) D25(-24,3) D26(-25,3) E1(0,4) E2(-1,4) E3(-2,4) E4(-3,4) E5(-4,4) E6(-5,4) E7(-6,4) E8(-7,4) E9(-8,4) E10(-9,4) E11(-10,4) E12(-11,4) E13(-12,4) E14(-13,4) E15(-14,4) E16(-15,4) E17(-16,4) E18(-17,4) E19(-18,4) E20(-19,4) E21(-20,4) E22(-21,4) E23(-22,4) E24(-23,4) E25(-24,4) E26(-25,4) F1(0,5) F2(-1,5) F3(-2,5) F4(-3,5) F5(-4,5) F6(-5,5) F7(-6,5) F8(-7,5) F9(-8,5) F10(-9,5) F11(-10,5) F12(-11,5) F13(-12,5) F14(-13,5) F15(-14,5) F16(-15,5) F17(-16,5) F18(-17,5) F19(-18,5) F20(-19,5) F21(-20,5) F22(-21,5) F23(-22,5) F24(-23,5) F25(-24,5) F26(-25,5) G1(0,6) G2(-1,6) G3(-2,6) G4(-3,6) G5(-4,6) G6(-5,6) G7(-6,6) G8(-7,6) G9(-8,6) G10(-9,6) G11(-10,6) G12(-11,6) G13(-12,6) G14(-13,6) G15(-14,6) G16(-15,6) G17(-16,6) G18(-17,6) G19(-18,6) G20(-19,6) G21(-20,6) G22(-21,6) G23(-22,6) G24(-23,6) G25(-24,6) G26(-25,6) H1(0,7) H2(-1,7) H3(-2,7) H4(-3,7) H5(-4,7) H6(-5,7) H7(-6,7) H20(-19,7) H21(-20,7) H22(-21,7) H23(-22,7) H24(-23,7) H25(-24,7) H26(-25,7) J1(0,8) J2(-1,8) J3(-2,8) J4(-3,8) J5(-4,8) J6(-5,8) J7(-6,8) J20(-19,8) J21(-20,8) J22(-21,8) J23(-22,8) J24(-23,8) J25(-24,8) J26(-25,8) K1(0,9) K2(-1,9) K3(-2,9) K4(-3,9) K5(-4,9) K6(-5,9) K7(-6,9) K20(-19,9) K21(-20,9) K22(-21,9) K23(-22,9) K24(-23,9) K25(-24,9) K26(-25,9) L1(0,10) L2(-1,10) L3(-2,10) L4(-3,10) L5(-4,10) L6(-5,10) L7(-6,10) L20(-19,10) L21(-20,10) L22(-21,10) L23(-22,10) L24(-23,10) L25(-24,10) L26(-25,10) M1(0,11) M2(-1,11) M3(-2,11) M4(-3,11) M5(-4,11) M6(-5,11) M7(-6,11) M12(-11,11) M13(-12,11) M14(-13,11) M15(-14,11) M20(-19,11) M21(-20,11) M22(-21,11) M23(-22,11) M24(-23,11) M25(-24,11) M26(-25,11) N1(0,12) N2(-1,12) N3(-2,12) N4(-3,12) N5(-4,12) N6(-5,12) N7(-6,12) N12(-11,12) N13(-12,12) N14(-13,12) N15(-14,12) N20(-19,12) N21(-20,12) N22(-21,12) N23(-22,12) N24(-23,12) N25(-24,12) N26(-25,12) P1(0,13) P2(-1,13) P3(-2,13) P4(-3,13) P5(-4,13) P6(-5,13) P7(-6,13) P12(-11,13) P13(-12,13) P14(-13,13) P15(-14,13) P20(-19,13) P21(-20,13) P22(-21,13) P23(-22,13) P24(-23,13) P25(-24,13) P26(-25,13) R1(0,14) R2(-1,14) R3(-2,14) R4(-3,14) R5(-4,14) R6(-5,14) R7(-6,14) R12(-11,14) R13(-12,14) R14(-13,14) R15(-14,14) R20(-19,14) R21(-20,14) R22(-21,14) R23(-22,14) R24(-23,14) R25(-24,14) R26(-25,14) T1(0,15) T2(-1,15) T3(-2,15) T4(-3,15) T5(-4,15) T6(-5,15) T7(-6,15) T20(-19,15) T21(-20,15) T22(-21,15) T23(-22,15) T24(-23,15) T25(-24,15) T26(-25,15) U1(0,16) U2(-1,16) U3(-2,16) U4(-3,16) U5(-4,16) U6(-5,16) U7(-6,16) U20(-19,16) U21(-20,16) U22(-21,16) U23(-22,16) U24(-23,16) U25(-24,16) U26(-25,16) V1(0,17) V2(-1,17) V3(-2,17) V4(-3,17) V5(-4,17) V6(-5,17) V7(-6,17) V20(-19,17) V21(-20,17) V22(-21,17) V23(-22,17) V24(-23,17) V25(-24,17) V26(-25,17) W1(0,18) W2(-1,18) W3(-2,18) W4(-3,18) W5(-4,18) W6(-5,18) W7(-6,18) W20(-19,18) W21(-20,18) W22(-21,18) W23(-22,18) W24(-23,18) W25(-24,18) W26(-25,18) Y1(0,19) Y2(-1,19) Y3(-2,19) Y4(-3,19) Y5(-4,19) Y6(-5,19) Y7(-6,19) Y8(-7,19) Y9(-8,19) Y10(-9,19) Y11(-10,19) Y12(-11,19) Y13(-12,19) Y14(-13,19) Y15(-14,19) Y16(-15,19) Y17(-16,19) Y18(-17,19) Y19(-18,19) Y20(-19,19) Y21(-20,19) Y22(-21,19) Y23(-22,19) Y24(-23,19) Y25(-24,19) Y26(-25,19)
  silkscreen extent -26,-1.02 1.8,26
HDR1X2 [mm] "Connector; Header; 2 Position"
  rect 1.5x1.5 hole 0.9: 1(0,0)
  round 1.5 hole 0.9: 2(2.54,0)
  silkscreen extent -1.27,-1.27 3.81,1.27
HDR2X2 [mm] "Connector; Header; 2x2 Position"
  rect 1.5x1.5 hole 0.9: 1(0,0)
  round 1.5 hole 0.9: 2(0,2.54) 3(2.54,0) 4(2.54,2.54)
  silkscreen extent -1.27,-1.27 3.81,3.81
HDR2X5 [mil]
  oct 62x62 hole 35: 1(0,0)
  round 62 hole 35: 2(0,100) 3(100,0) 4(100,100) 5(200,0) 6(200,100) 7(300,0) 8(300,100) 9(400,0) 10(400,100)
  silkscreen extent -50,-50 450,150
HDR2X6 [mm] "Connector; Header; 6x2 Position"
  rect 1.5x1.5 hole 0.9: 1(0,0)
  round 1.5 hole 0.9: 2(0,2.54) 3(2.54,0) 4(2.54,2.54) 5(5.08,0) 6(5.08,2.54) 7(7.62,0) 8(7.62,2.54) 9(10.16,0) 10(10.16,2.54) 11(12.7,0) 12(12.7,2.54)
  silkscreen extent -1.27,-1.27 13.97,3.81
HDR2X7 [mm] "Connector; Header; 7x2 Position"
  rect 1.5x1.5 hole 0.9: 1(0,0)
  round 1.5 hole 0.9: 2(0,2.54) 3(2.54,0) 4(2.54,2.54) 5(5.08,0) 6(5.08,2.54) 7(7.62,0) 8(7.62,2.54) 9(10.16,0) 10(10.16,2.54) 11(12.7,0) 12(12.7,2.54) 13(15.24,0) 14(15.24,2.54)
  silkscreen extent -1.27,-1.27 16.51,3.81
HEADER2X2 [mm]
  rect 1.5x1.5 hole 0.9: 1(0,0)
  round 1.5 hole 0.9: 2(0,2.54) 3(2.54,0) 4(2.54,2.54)
  silkscreen extent -1.27,-1.27 3.81,3.81
L44.7uH [mm] "for L4"
  rect 3.5x3.5 smd: 1(0,0) 2(10,0)
  silkscreen extent -1.78,-5 11.81,5
LM1117 [mil]
  rect 90x42 smd: 1(-250,141)
  oval 90x42 smd: 2(-250,51) 3(-250,-39)
  rect 100x130 smd: 4(-20,51)
  silkscreen extent -184,-84 -85,186
OSC [mm]
  rect 2x3 smd: 1(-5,2.134) 2(-5,-2.87) 3(0,-2.866) 4(0,2.134)
  silkscreen extent -6.22,-4.52 1.19,4.48
OSC50MHz [mm] "for 50MHz"
  rect 2x3 smd: 1(-5,2.134) 2(-5,-2.87) 3(0,-2.866) 4(0,2.134)
  silkscreen extent -6.22,-4.52 1.19,4.48
PCI2-H121 [mm]
  round 1.3 hole 0.7: A1(21,-5) A2(19,-5) A3(17,-5) A4(15,-5) A5(13,-5) A6(11,-5) A7(9,-5) A8(7,-5) A9(5,-5) A10(3,-5) A11(1,-5) A12(-1,-5) A13(-3,-5) A14(-5,-5) A15(-7,-5) A16(-9,-5) A17(-11,-5) A18(-13,-5) A19(-15,-5) A20(-17,-5) A21(-19,-5) A22(-21,-5) B1(21,-3) B2(19,-3) B3(17,-3) B4(15,-3) B5(13,-3) B6(11,-3) B7(9,-3) B8(7,-3) B9(5,-3) B10(3,-3) B11(1,-3) B12(-1,-3) B13(-3,-3) B14(-5,-3) B15(-7,-3) B16(-9,-3) B17(-11,-3) B18(-13,-3) B19(-15,-3) B20(-17,-3) B21(-19,-3) B22(-21,-3) C1(21,-1) C2(19,-1) C3(17,-1) C4(15,-1) C5(13,-1) C6(11,-1) C7(9,-1) C8(7,-1) C9(5,-1) C10(3,-1) C11(1,-1) C12(-1,-1) C13(-3,-1) C14(-5,-1) C15(-7,-1) C16(-9,-1) C17(-11,-1) C18(-13,-1) C19(-15,-1) C20(-17,-1) C21(-19,-1) C22(-21,-1) D1(21,1) D2(19,1) D3(17,1) D4(15,1) D5(13,1) D6(11,1) D7(9,1) D8(7,1) D9(5,1) D10(3,1) D11(1,1) D12(-1,1) D13(-3,1) D14(-5,1) D15(-7,1) D16(-9,1) D17(-11,1) D18(-13,1) D19(-15,1) D20(-17,1) D21(-19,1) D22(-21,1) E1(21,3) E2(19,3) E3(17,3) E4(15,3) E5(13,3) E6(11,3) E7(9,3) E8(7,3) E9(5,3) E10(3,3) E11(1,3) E12(-1,3) E13(-3,3) E14(-5,3) E15(-7,3) E16(-9,3) E17(-11,3) E18(-13,3) E19(-15,3) E20(-17,3) E21(-19,3) E22(-21,3) F1(21,5) F3(17,5) F5(13,5) F7(9,5) F9(5,5) F11(1,5) F13(-3,5) F15(-7,5) F17(-11,5) F19(-15,5) F21(-19,5)
  silkscreen extent -22,-6.5 20.93,6.05
PCI2-H123 [mm]
  round 1.3 hole 0.7: A1(24,-5) A2(22,-5) A3(20,-5) A4(18,-5) A5(16,-5) A6(14,-5) A7(12,-5) A8(10,-5) A9(8,-5) A10(6,-5) A11(4,-5) A15(-4,-5) A16(-6,-5) A17(-8,-5) A18(-10,-5) A19(-12,-5) A20(-14,-5) A21(-16,-5) A22(-18,-5) A23(-20,-5) A24(-22,-5) A25(-24,-5) B1(24,-3) B2(22,-3) B3(20,-3) B4(18,-3) B5(16,-3) B6(14,-3) B7(12,-3) B8(10,-3) B9(8,-3) B10(6,-3) B11(4,-3) B15(-4,-3) B16(-6,-3) B17(-8,-3) B18(-10,-3) B19(-12,-3) B20(-14,-3) B21(-16,-3) B22(-18,-3) B23(-20,-3) B24(-22,-3) B25(-24,-3) C1(24,-1) C2(22,-1) C3(20,-1) C4(18,-1) C5(16,-1) C6(14,-1) C7(12,-1) C8(10,-1) C9(8,-1) C10(6,-1) C11(4,-1) C15(-4,-1) C16(-6,-1) C17(-8,-1) C18(-10,-1) C19(-12,-1) C20(-14,-1) C21(-16,-1) C22(-18,-1) C23(-20,-1) C24(-22,-1) C25(-24,-1) D1(24,1) D2(22,1) D3(20,1) D4(18,1) D5(16,1) D6(14,1) D7(12,1) D8(10,1) D9(8,1) D10(6,1) D11(4,1) D15(-4,1) D16(-6,1) D17(-8,1) D18(-10,1) D19(-12,1) D20(-14,1) D21(-16,1) D22(-18,1) D23(-20,1) D24(-22,1) D25(-24,1) E1(24,3) E2(22,3) E3(20,3) E4(18,3) E5(16,3) E6(14,3) E7(12,3) E8(10,3) E9(8,3) E10(6,3) E11(4,3) E15(-4,3) E16(-6,3) E17(-8,3) E18(-10,3) E19(-12,3) E20(-14,3) E21(-16,3) E22(-18,3) E23(-20,3) E24(-22,3) E25(-24,3) F1(24,5) F3(20,5) F5(16,5) F7(12,5) F9(8,5) F11(4,5) F13(0,5) F15(-4,5) F17(-8,5) F19(-12,5) F21(-16,5) F23(-20,5) F25(-24,5)
  silkscreen extent -24.03,-6.5 25,6.1
POWER_CON [mm] "for power input"
  rect 3.8x3.8 hole 2.5: 1(0,0) 2(6.5,0) 3(3.25,4.5)
  silkscreen extent -1.98,-3.56 13.31,6.78
PQFP240 [mm] "240-Pin Plastic Quad Flat Pack (PQFP)"
  rect 1.5x0.3 smd: 1(-16.975,14.75) 2(-16.975,14.25) 3(-16.975,13.75) 4(-16.975,13.25) 5(-16.975,12.75) 6(-16.975,12.25) 7(-16.975,11.75) 8(-16.975,11.25) 9(-16.975,10.75) 10(-16.975,10.25) 11(-16.975,9.75) 12(-16.975,9.25) 13(-16.975,8.75) 14(-16.975,8.25) 15(-16.975,7.75) 16(-16.975,7.25) 17(-16.975,6.75) 18(-16.975,6.25) 19(-16.975,5.75) 20(-16.975,5.25) 21(-16.975,4.75) 22(-16.975,4.25) 23(-16.975,3.75) 24(-16.975,3.25) 25(-16.975,2.75) 26(-16.975,2.25) 27(-16.975,1.75) 28(-16.975,1.25) 29(-16.975,0.75) 30(-16.975,0.25) 31(-16.975,-0.25) 32(-16.975,-0.75) 33(-16.975,-1.25) 34(-16.975,-1.75) 35(-16.975,-2.25) 36(-16.975,-2.75) 37(-16.975,-3.25) 38(-16.975,-3.75) 39(-16.975,-4.25) 40(-16.975,-4.75) 41(-16.975,-5.25) 42(-16.975,-5.75) 43(-16.975,-6.25) 44(-16.975,-6.75) 45(-16.975,-7.25) 46(-16.975,-7.75) 47(-16.975,-8.25) 48(-16.975,-8.75) 49(-16.975,-9.25) 50(-16.975,-9.75) 51(-16.975,-10.25) 52(-16.975,-10.75) 53(-16.975,-11.25) 54(-16.975,-11.75) 55(-16.975,-12.25) 56(-16.975,-12.75) 57(-16.975,-13.25) 58(-16.975,-13.75) 59(-16.975,-14.25) 60(-16.975,-14.75) 121(16.975,-14.75) 122(16.975,-14.25) 123(16.975,-13.75) 124(16.975,-13.25) 125(16.975,-12.75) 126(16.975,-12.25) 127(16.975,-11.75) 128(16.975,-11.25) 129(16.975,-10.75) 130(16.975,-10.25) 131(16.975,-9.75) 132(16.975,-9.25) 133(16.975,-8.75) 134(16.975,-8.25) 135(16.975,-7.75) 136(16.975,-7.25) 137(16.975,-6.75) 138(16.975,-6.25) 139(16.975,-5.75) 140(16.975,-5.25) 141(16.975,-4.75) 142(16.975,-4.25) 143(16.975,-3.75) 144(16.975,-3.25) 145(16.975,-2.75) 146(16.975,-2.25) 147(16.975,-1.75) 148(16.975,-1.25) 149(16.975,-0.75) 150(16.975,-0.25) 151(16.975,0.25) 152(16.975,0.75) 153(16.975,1.25) 154(16.975,1.75) 155(16.975,2.25) 156(16.975,2.75) 157(16.975,3.25) 158(16.975,3.75) 159(16.975,4.25) 160(16.975,4.75) 161(16.975,5.25) 162(16.975,5.75) 163(16.975,6.25) 164(16.975,6.75) 165(16.975,7.25) 166(16.975,7.75) 167(16.975,8.25) 168(16.975,8.75) 169(16.975,9.25) 170(16.975,9.75) 171(16.975,10.25) 172(16.975,10.75) 173(16.975,11.25) 174(16.975,11.75) 175(16.975,12.25) 176(16.975,12.75) 177(16.975,13.25) 178(16.975,13.75) 179(16.975,14.25) 180(16.975,14.75)
  rect 0.3x1.5 smd: 61(-14.75,-16.975) 62(-14.25,-16.975) 63(-13.75,-16.975) 64(-13.25,-16.975) 65(-12.75,-16.975) 66(-12.25,-16.975) 67(-11.75,-16.975) 68(-11.25,-16.975) 69(-10.75,-16.975) 70(-10.25,-16.975) 71(-9.75,-16.975) 72(-9.25,-16.975) 73(-8.75,-16.975) 74(-8.25,-16.975) 75(-7.75,-16.975) 76(-7.25,-16.975) 77(-6.75,-16.975) 78(-6.25,-16.975) 79(-5.75,-16.975) 80(-5.25,-16.975) 81(-4.75,-16.975) 82(-4.25,-16.975) 83(-3.75,-16.975) 84(-3.25,-16.975) 85(-2.75,-16.975) 86(-2.25,-16.975) 87(-1.75,-16.975) 88(-1.25,-16.975) 89(-0.75,-16.975) 90(-0.25,-16.975) 91(0.25,-16.975) 92(0.75,-16.975) 93(1.25,-16.975) 94(1.75,-16.975) 95(2.25,-16.975) 96(2.75,-16.975) 97(3.25,-16.975) 98(3.75,-16.975) 99(4.25,-16.975) 100(4.75,-16.975) 101(5.25,-16.975) 102(5.75,-16.975) 103(6.25,-16.975) 104(6.75,-16.975) 105(7.25,-16.975) 106(7.75,-16.975) 107(8.25,-16.975) 108(8.75,-16.975) 109(9.25,-16.975) 110(9.75,-16.975) 111(10.25,-16.975) 112(10.75,-16.975) 113(11.25,-16.975) 114(11.75,-16.975) 115(12.25,-16.975) 116(12.75,-16.975) 117(13.25,-16.975) 118(13.75,-16.975) 119(14.25,-16.975) 120(14.75,-16.975) 181(14.75,16.975) 182(14.25,16.975) 183(13.75,16.975) 184(13.25,16.975) 185(12.75,16.975) 186(12.25,16.975) 187(11.75,16.975) 188(11.25,16.975) 189(10.75,16.975) 190(10.25,16.975) 191(9.75,16.975) 192(9.25,16.975) 193(8.75,16.975) 194(8.25,16.975) 195(7.75,16.975) 196(7.25,16.975) 197(6.75,16.975) 198(6.25,16.975) 199(5.75,16.975) 200(5.25,16.975) 201(4.75,16.975) 202(4.25,16.975) 203(3.75,16.975) 204(3.25,16.975) 205(2.75,16.975) 206(2.25,16.975) 207(1.75,16.975) 208(1.25,16.975) 209(0.75,16.975) 210(0.25,16.975) 211(-0.25,16.975) 212(-0.75,16.975) 213(-1.25,16.975) 214(-1.75,16.975) 215(-2.25,16.975) 216(-2.75,16.975) 217(-3.25,16.975) 218(-3.75,16.975) 219(-4.25,16.975) 220(-4.75,16.975) 221(-5.25,16.975) 222(-5.75,16.975) 223(-6.25,16.975) 224(-6.75,16.975) 225(-7.25,16.975) 226(-7.75,16.975) 227(-8.25,16.975) 228(-8.75,16.975) 229(-9.25,16.975) 230(-9.75,16.975) 231(-10.25,16.975) 232(-10.75,16.975) 233(-11.25,16.975) 234(-11.75,16.975) 235(-12.25,16.975) 236(-12.75,16.975) 237(-13.25,16.975) 238(-13.75,16.975) 239(-14.25,16.975) 240(-14.75,16.975)
  silkscreen extent -17.1,-15.83 15.83,15.83
PWP20 [mm] "PWP20;PSO;PWP (R-PDSO-G**);for TPS54310"
  rect 2x0.4 smd: 1(0,0)
  rect 2.032x3.81 smd: 1(3.302,-2.921)
  oval 2x0.4 smd: 2(0,-0.65) 3(0,-1.3) 4(0,-1.95) 5(0,-2.6) 6(0,-3.25) 7(0,-3.9) 8(0,-4.55) 9(0,-5.2) 10(0,-5.85)
  oval 2.2x0.4 smd: 11(6.6,-5.85) 12(6.6,-5.2) 13(6.6,-4.55) 14(6.6,-3.9) 15(6.6,-3.25) 16(6.6,-2.6) 17(6.6,-1.95) 18(6.6,-1.3) 19(6.6,-0.65) 20(6.6,0)
  silkscreen extent 2.08,-6.18 4.51,0.33
QFP44_2 [mm]
  oval 2.5x0.4 smd: 1(0,0)
  rect 2.5x0.4 smd: 2(0,-0.8) 3(0,-1.6) 4(0,-2.4) 5(0,-3.2) 6(0,-4) 7(0,-4.8) 8(0,-5.6) 9(0,-6.4) 10(0,-7.2) 11(0,-8) 23(12.9,-8) 24(12.9,-7.2) 25(12.9,-6.4) 26(12.9,-5.6) 27(12.9,-4.8) 28(12.9,-4) 29(12.9,-3.2) 30(12.9,-2.4) 31(12.9,-1.6) 32(12.9,-0.8) 33(12.9,0)
  rect 0.4x2.5 smd: 12(2.45,-10.45) 13(3.25,-10.45) 14(4.05,-10.45) 15(4.85,-10.45) 16(5.65,-10.45) 17(6.45,-10.45) 18(7.25,-10.45) 19(8.05,-10.45) 20(8.85,-10.45) 21(9.65,-10.45) 22(10.45,-10.45) 34(10.45,2.45) 35(9.65,2.45) 36(8.85,2.45) 37(8.05,2.45) 38(7.25,2.45) 39(6.45,2.45) 40(5.65,2.45) 41(4.85,2.45) 42(4.05,2.45) 43(3.25,2.45) 44(2.45,2.45)
  silkscreen extent 1.78,-8.67 11.12,0.66
R0603_4 [mil] "for ResPackX4____OK!"
  rect 35x18 smd: 1(0,0) 2(0,-36) 3(0,-72) 4(0,-108) 5(70.16,-108) 6(70.16,-72) 7(70.16,-36) 8(70.16,0)
  silkscreen extent -33,-123 99,15
RCA [mm]
  round 3.5 hole 2.1: 1(4.433,-1.168) 1(4.433,2.832) 2(-1.067,-1.168)
  silkscreen extent -6.91,-6.2 6.43,4.83
SMA [mm]
  round 3 hole 1.8: 1(0,0) 2(-2.5,-2.5) 2(-2.5,2.5) 2(2.5,-2.5) 2(2.5,2.5)
  silkscreen extent -4.5,-4.8 4.5,4.6
"SMD _LED" [mm]
  rect 1.3x1.6 smd: 1(0.95,0) 2(-0.95,0)
  silkscreen extent -2.13,-1.15 2,1.15
"SO-G3 for NPN" [mm]
  rect 0.9x1.27 smd: 1(0,1.25)
  rect 0.9x0.95 smd: 2(-0.95,-1.25) 3(0.95,-1.25)
  silkscreen extent -2.07,-1.37 1.3,1.25
SO-G8 [mm]
  rect 0.6x2.2 smd: 1(-1.905,-2.6) 2(-0.635,-2.6) 3(0.635,-2.6) 4(1.905,-2.6) 5(1.905,2.6) 6(0.635,2.6) 7(-0.635,2.6) 8(-1.905,2.6)
  silkscreen extent -2.88,-2.72 2.5,1.1
SOIC8 [mm] "8-Pin Small-Outline Integrated Circuit (SOIC)"
  rect 0.6x2.2 smd: 1(-1.905,-2.6) 2(-0.635,-2.6) 3(0.635,-2.6) 4(1.905,-2.6) 5(1.905,2.6) 6(0.635,2.6) 7(-0.635,2.6) 8(-1.905,2.6)
  silkscreen extent -2.88,-2.72 2.5,1.1
SOT23-5S [mil] "for TPS75733"
  oval 200x50 smd: 1(0,0) 2(0,-67) 3(0,-134) 4(0,-201) 5(0,-268)
  rect 400x400 smd: 3(375,-135)
  silkscreen extent 130,-360 580,95
SSOP48 [mm]
  rect 2x0.28 smd: 1(0,0)
  oval 2x0.28 smd: 2(0,-0.5) 3(0,-1) 4(0,-1.5) 5(0,-2) 6(0,-2.5) 7(0,-3) 8(0,-3.5) 9(0,-4) 10(0,-4.5) 11(0,-5) 12(0,-5.5) 13(0,-6) 14(0,-6.5) 15(0,-7) 16(0,-7.5) 17(0,-8) 18(0,-8.5) 19(0,-9) 20(0,-9.5) 21(0,-10) 22(0,-10.5) 23(0,-11) 24(0,-11.5) 25(8,-11.5) 26(8,-11) 27(8,-10.5) 28(8,-10) 29(8,-9.5) 30(8,-9) 31(8,-8.5) 32(8,-8) 33(8,-7.5) 34(8,-7) 35(8,-6.5) 36(8,-6) 37(8,-5.5) 38(8,-5) 39(8,-4.5) 40(8,-4) 41(8,-3.5) 42(8,-3) 43(8,-2.5) 44(8,-2) 45(8,-1.5) 46(8,-1) 47(8,-0.5) 48(8,0)
  silkscreen extent 1.84,-11.75 6.16,0.25
TSOP48 [mm] "for Am29LV800B"
  rect 2x0.3 smd: 1(0,0)
  oval 2x0.3 smd: 2(0,-0.5) 3(0,-1) 4(0,-1.5) 5(0,-2) 6(0,-2.5) 7(0,-3) 8(0,-3.5) 9(0,-4) 10(0,-4.5) 11(0,-5) 12(0,-5.5) 13(0,-6) 14(0,-6.5) 15(0,-7) 16(0,-7.5) 17(0,-8) 18(0,-8.5) 19(0,-9) 20(0,-9.5) 21(0,-10) 22(0,-10.5) 23(0,-11) 24(0,-11.5) 25(20.2,-11.5) 26(20.2,-11) 27(20.2,-10.5) 28(20.2,-10) 29(20.2,-9.5) 30(20.2,-9) 31(20.2,-8.5) 32(20.2,-8) 33(20.2,-7.5) 34(20.2,-7) 35(20.2,-6.5) 36(20.2,-6) 37(20.2,-5.5) 38(20.2,-5) 39(20.2,-4.5) 40(20.2,-4) 41(20.2,-3.5) 42(20.2,-3) 43(20.2,-2.5) 44(20.2,-2) 45(20.2,-1.5) 46(20.2,-1) 47(20.2,-0.5) 48(20.2,0)
  silkscreen extent 2.08,-11.75 18.12,0.25
TSOP86 [mm] "TSOP;43*2;for HY57V283220"
  rect 2x0.3 smd: 1(0,0)
  oval 2x0.3 smd: 2(0,-0.5) 3(0,-1) 4(0,-1.5) 5(0,-2) 6(0,-2.5) 7(0,-3) 8(0,-3.5) 9(0,-4) 10(0,-4.5) 11(0,-5) 12(0,-5.5) 13(0,-6) 14(0,-6.5) 15(0,-7) 16(0,-7.5) 17(0,-8) 18(0,-8.5) 19(0,-9) 20(0,-9.5) 21(0,-10) 22(0,-10.5) 23(0,-11) 24(0,-11.5) 25(0,-12) 26(0,-12.5) 27(0,-13) 28(0,-13.5) 29(0,-14) 30(0,-14.5) 31(0,-15) 32(0,-15.5) 33(0,-16) 34(0,-16.5) 35(0,-17) 36(0,-17.5) 37(0,-18) 38(0,-18.5) 39(0,-19) 40(0,-19.5) 41(0,-20) 42(0,-20.5) 43(0,-21) 44(11.938,-21) 45(11.938,-20.5) 46(11.938,-20) 47(11.938,-19.5) 48(11.938,-19) 49(11.938,-18.5) 50(11.938,-18) 51(11.938,-17.5) 52(11.938,-17) 53(11.938,-16.5) 54(11.938,-16) 55(11.938,-15.5) 56(11.938,-15) 57(11.938,-14.5) 58(11.938,-14) 59(11.938,-13.5) 60(11.938,-13) 61(11.938,-12.5) 62(11.938,-12) 63(11.938,-11.5) 64(11.938,-11) 65(11.938,-10.5) 66(11.938,-10) 67(11.938,-9.5) 68(11.938,-9) 69(11.938,-8.5) 70(11.938,-8) 71(11.938,-7.5) 72(11.938,-7) 73(11.938,-6.5) 74(11.938,-6) 75(11.938,-5.5) 76(11.938,-5) 77(11.938,-4.5) 78(11.938,-4) 79(11.938,-3.5) 80(11.938,-3) 81(11.938,-2.5) 82(11.938,-2) 83(11.938,-1.5) 84(11.938,-1) 85(11.938,-0.5) 86(11.938,0)
  silkscreen extent -0.22,-21.25 9.85,0.73

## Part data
C1 C2 C3 C4 C5 C6 C7 C8 C9 C10 C11 C16 C17 C18 C19 C20 C21 C22 C23 C24 C25 C26 C27 C37 C38 C39 C40 C41 C42 C43 C44 C45 C46 C47 C48 C49 C50 C51 C52 C53 C54 C55 C56 C57 C58 C59 C60 C63 C64 C65 C66 C67 C68 C69 C70 C71 C72 C73 C74 C75 C76 C77 C78 C79 C80 C81 C82 C83 C84 C85 C86 C87 C90 C95 C96 C97 C98 C99 C100 C101 C102 C103 C104 C105 C106 C107 C108 C109 C110 C111 C112 C113 C114 C115 C116 C117 C118 C119 C120 C121 C122 C123 C124 C125 C126 C127 C128 C129 C130 C131 C132 C133 C153 C154 C155 C156 C157 C158 C159 C160 C161 C162 C163 C165 C166: "Capacitor"
C14 C15 C144 C145 C146 C147 C148 C149 C150 C151 C152 C164: "Polarized Capacitor (Axial)"
C134 C135 C136 C137 C138 C139 C140 C141 C142 C143: "Polarized Capacitor (Radial)"
DS1 DS2 DS3: "Typical RED, GREEN, YELLOW, AMBER GaAs LED"
DS6 DS9: "Typical BLUE SiC LED"
FB1 FB2 FB3 FB4 FB5 FB6 FB7 FB8: library part Inductor, "Inductor"
J1: library part "Header 7X2", "Header, 7-Pin, Dual row"
J2: "Z-Pack 2mm Hard Metric Type A 110 Position Female PCB Mount Connector"
J4: "RCA Connector"
J5: "Z-Pack 2mm Hard Metric Type B 110 Position Female Daughter Card Connector"
JP1 JP2 JP7 JP8 JP9 JP11 JP13: "Header, 2-Pin"
JP3 JP4 JP5: library part "Header 5X2", "Header, 5-Pin, Dual row"
JP6: "Header, 6-Pin, Dual row"
JP10 JP12: "Header, 2-Pin, Dual row"
L1: "Magnetic-Core Inductor"
Q1: library part QNPN, "NPN Bipolar Transistor"
R1 R2 R3 R4 R5 R6 R7 R8 R11 R12 R13 R14 R15 R16 R17 R18 R19 R20 R21 R22 R23 R24 R25 R26 R27 R28 R29 R39 R40 R41 R42 R43 R46 R53 R55 R56 R57 R58 R59 R60 R61 R62 R63 R64 R65 R66 R67 R68 R69 R70 R71 R72 R73 R74 R75 R76 R77 R78 R79 R80 R81 R82 R83 R84 R85 R86 R87 R88 R89 R90 R91: "Resistor"
R30 R31 R32 R33 R34 R35 R36 R37 R38 R47 R48 R49 R50 R51 R52 R54: "Resistor Array - Parts"
S1: "DIP Switch"
S2: "Switch"
U2: "Cyclone Family, 1.5V FPGA, 173 I/O Pins, 2 x PLLs, Commercial Grade, Speed Grade 6"
U3: "Hotlink II"
U4 U6: library part Oscillator
U5: "EPCS1 Series, In-system programmable 3.3V configuration device, 8-Pin SOIC, 1-Megabit, Industrial Grade"
U8: "by TX"
U16 U17: library part "Volt Reg", "Voltage Regulator"
U20: library part "EMI filter"

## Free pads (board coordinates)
  rect 236.22x314.96 smd: 0(4125,6193)
  round 50 hole 110: 1(4140,9717) 2(4140,6217)
  round 60 hole 30: 1(9344,6431) 2(9345,6353) 3(9347,6274) 4(9347,6195)
  round 60 hole 40: 5(4371,6209) 6(5190,9707) 7(9511,9700) 8(9343,6522) 9(6520,9490)
  rect 1259.84x59.06 smd: 10(4609,6031)
  rect 1259.84x59.05 smd far side: 10(4609,6031)
  rect 2165.35x59.05 smd far side: 11(6528,6033)
  rect 2165.35x59.05 smd: 11(6532,6033)
  rect 1574.8x59.05 smd: 12(9525,6027)
  rect 1574.8x59.05 smd far side: 12(9525,6027)

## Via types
v1: diameter 16, hole 8, TopLayer to BottomLayer, 408 vias
v2: diameter 20, hole 10, TopLayer to BottomLayer, 220 vias
v3: diameter 24, hole 12, TopLayer to BottomLayer, 196 vias
v4: diameter 56.69, hole 56.69, TopLayer to BottomLayer, 2 vias
v5: diameter 20, hole 0, TopLayer to BottomLayer, 1 vias

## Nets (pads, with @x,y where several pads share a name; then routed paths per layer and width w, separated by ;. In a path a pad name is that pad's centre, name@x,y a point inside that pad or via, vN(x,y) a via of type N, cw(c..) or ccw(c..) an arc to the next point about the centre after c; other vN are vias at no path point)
1.4VPWRGD: R64.2 R72.2 U15.4 | length 866.2
  TopLayer w12: R72.2@7973.46,9500 8075,9500 8086.54,9511.54 R64.2@8086.54,9600 ; U15.4@8536.77,9180 v3(8536.77,9237.23)
  BottomLayer w12: v3(8043,9500) 8305.77,9237.23 v3(8536.77,9237.23)
101_BISTLE: U2.113 U3.E1 | length 746.3
  TopLayer w6: U2.113@5163.09,8922.31 5163.09,8986.09 5572.52,9395.52 U3.E1@5676,9395.52
101_BOE0: U2.115 U3.D1 | length 816.4
  TopLayer w6: U2.115@5123.72,8922.31 5123.72,9010.72 5547.89,9434.89 U3.D1@5676,9434.89
101_BOE1: U2.116 U3.D2 | length 899
  TopLayer w6: U2.116@5104.03,8922.31 5104.03,9021.03 5539,9456 5694.26,9456 U3.D2@5715.37,9434.89
101_CLK: R13.1 R25.2 U3.F10 | length 415
  TopLayer w8: U3.F10@6030.33,9356.15 6310.39,9356.15 6340,9326.54 R13.1@6340,9233.46
101_DECOMDE: U2.114 U3.E2 | length 828.1
  TopLayer w6: U2.114@5143.4,8922.31 5143.4,8997.4 5561,9415 5695.89,9415 U3.E2@5715.37,9395.52
101_FRAMCHAR: U2.106 U3.D3 | length 791.3
  TopLayer w6: U2.106@5300.88,8922.31 v1(5300.88,8973.88) ; v1(5734.85,9415) U3.D3@5754.74,9434.89
  BottomLayer w6: v1(5300.88,8973.88) 5300.88,9135.88 5580,9415 v1(5734.85,9415)
101_INSEL: U2.49 U3.C10 | length 1291
  TopLayer w6: U3.C10@6030.33,9474.26 v1(6127.74,9474.26) ; U2.49@6274.31,8618.17 v1(6470,8618.17)
  BottomLayer w6: v1(6127.74,9474.26) 6470,9132 v1(6470,8618.17)
101_L\F\I\: U2.74 U3.H4 | length 428.4
  TopLayer w6: v1(5774,9257.3) U3.H4@5794.11,9277.41 ; U2.74@5930.8,8922.31 v1(5930.8,8986.2)
  BottomLayer w6: v1(5774,9257.3) 5774,9143 v1(5930.8,8986.2)
101_LPEN: U2.118 U3.C2 | length 971.1
  TopLayer w6: U2.118@5064.66,8922.31 5064.66,9049.66 5510,9495 5694.63,9495 U3.C2@5715.37,9474.26
101_OELE: U2.95 U3.E3 | length 660.1
  TopLayer w6: U2.95@5517.42,8922.31 v1(5517.42,8974.42) ; v1(5736.22,9377) U3.E3@5754.74,9395.52
  BottomLayer w6: v1(5517.42,8974.42) 5517.42,9309.42 5585,9377 v1(5736.22,9377)
101_PARCTL: U2.54 U3.C8 | length 1154.4
  TopLayer w6: U3.C8@5951.59,9474.26 v1(5970.85,9455) ; U2.54@6274.31,8716.6 v1(6418,8716.6)
  BottomLayer w6: v1(5970.85,9455) 5990.85,9435 6093,9435 6418,9110 v1(6418,8716.6)
101_REFCLK+: R13.2 U2.60 | length 382.7
  TopLayer w8: U2.60@6274.31,8834.71 6314.71,8834.71 6340,8860 R13.2@6340,9166.54
101_RFEN: U2.117 U3.C1 | length 886.5
  TopLayer w6: U2.117@5084.35,8922.31 5084.35,9035.35 5523.26,9474.26 U3.C1@5676,9474.26
101_RFMODE: U2.48 U3.C9 | length 1410.6
  TopLayer w6: U3.C9@5990.96,9474.26 6011.7,9495 6140,9495 v1(6157,9478) ; U2.48@6274.31,8598.49 v1(6487,8598.49)
  BottomLayer w6: v1(6157,9478) 6487,9148 v1(6487,8598.49)
101_RXCKSEL: U2.57 U3.E9 | length 917.4
  TopLayer w6: U3.E9@5990.96,9395.52 6009.48,9377 v1(6009.48,9339.52) ; U2.57@6274.31,8775.65 v1(6364,8775.65)
  BottomLayer w6: v1(6009.48,9339.52) 6012,9337 6103,9337 6364,9076 v1(6364,8775.65)
101_RXCLK+: U2.83 U3.K4 | length 293.1
  TopLayer w6: U2.83@5753.64,8922.31 5753.64,8968.64 5794.11,9009.11 U3.K4@5794.11,9198.67
101_RXCLK-: U2.84 U3.J4 | length 340.7
  TopLayer w6: U2.84@5733.95,8922.31 5733.95,8980.95 5774,9021 5774,9217.93 U3.J4@5794.11,9238.04
101_RXCLKC+: U2.107 U3.C4 | length 870.2
  TopLayer w6: U2.107@5281.2,8922.31 v1(5281.2,8998.32) ; v1(5775.85,9456) U3.C4@5794.11,9474.26
  BottomLayer w6: v1(5281.2,8998.32) 5281.2,9142 5340.59,9201.39 5575.2,9436 5755.85,9436 v1(5775.85,9456)
101_RXD0: U2.98 U3.H1 | length 475.5
  TopLayer w6: U2.98@5458.36,8922.31 5458.36,9111.36 5624.41,9277.41 U3.H1@5676,9277.41
101_RXD1: U2.101 U3.G2 | length 620.1
  TopLayer w6: U2.101@5399.31,8922.31 5399.31,9132.31 5605,9338 5694.15,9338 U3.G2@5715.37,9316.78
101_RXD2: U2.99 U3.H2 | length 554.5
  TopLayer w6: U2.99@5438.68,8922.31 5438.68,9117.68 5618,9297 5695.78,9297 U3.H2@5715.37,9277.41
101_RXD3: U2.87 U3.J2 | length 332.5
  TopLayer w6: U2.87@5674.9,8922.31 5674.9,8997.9 5695,9018 5695,9217.67 U3.J2@5715.37,9238.04
101_RXD4: U2.86 U3.K2 | length 285
  TopLayer w6: U2.86@5694.58,8922.31 5694.58,8995.58 5715.37,9016.37 U3.K2@5715.37,9198.67
101_RXD5: U2.93 U3.G3 | length 565.5
  TopLayer w6: U2.93@5556.79,8922.31 v1(5556.79,8973.79) ; v1(5734.96,9297) U3.G3@5754.74,9316.78
  BottomLayer w6: v1(5556.79,8973.79) 5556.79,9270.79 5583,9297 v1(5734.96,9297)
101_RXD6: U2.88 U3.H3 | length 540.1
  TopLayer w6: U2.88@5655.21,8922.31 v1(5655.21,8968.79) ; v1(5735,9257.67) U3.H3@5754.74,9277.41
  BottomLayer w6: v1(5655.21,8968.79) 5576,9048 5576,9232 5601.67,9257.67 v1(5735,9257.67)
101_RXD7: U2.85 U3.J3 | length 332.5
  TopLayer w6: U2.85@5714.27,8922.31 5714.27,8987.27 5735,9008 5735,9218.3 U3.J3@5754.74,9238.04
101_RXLE: U2.108 U3.C3 | length 856.7
  TopLayer w6: U2.108@5261.51,8922.31 5262,8922.8 v1(5262,8974) ; v1(5736.48,9456) U3.C3@5754.74,9474.26
  BottomLayer w6: v1(5262,8974) 5262,9153 5565,9456 v1(5736.48,9456)
101_RXMODE: U2.45 U3.A5 | length 1827.4
  TopLayer w6: U3.A5@5833.48,9553 5833.48,9574.48 v1(5837,9578) ; U2.45@6274.31,8539.43 v1(6547,8539.43)
  BottomLayer w6: v1(5837,9578) 5856,9597 5900,9597 5972,9525 6197,9525 6547,9175 v1(6547,8539.43)
101_RXOP: U2.100 U3.G1 | length 540.9
  TopLayer w6: U2.100@5418.99,8922.31 5418.99,9127.99 5607.78,9316.78 U3.G1@5676,9316.78
101_RXRATE: U2.119 U3.C5 | length 1059.8
  TopLayer w6: U2.119@5044.98,8922.31 v1(5044.98,8967.98) ; v1(5813.74,9494) U3.C5@5833.48,9474.26
  BottomLayer w6: v1@5044.98,8968.98 5570,9494 v1(5813.74,9494)
101_RXST0: U2.94 U3.F3 | length 611
  TopLayer w6: U2.94@5537.1,8922.31 v1(5537.1,8995.1) ; v1(5736.59,9338) U3.F3@5754.74,9356.15
  BottomLayer w6: v1(5537.1,8995.1) 5537.1,9287.1 5588,9338 v1(5736.59,9338)
101_RXST1: U2.105 U3.F2 | length 703.8
  TopLayer w6: U2.105@5320.57,8922.31 5320.57,9113.57 5584,9377 5694.52,9377 U3.F2@5715.37,9356.15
